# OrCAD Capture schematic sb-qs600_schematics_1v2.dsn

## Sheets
1 01. Index: title: SB-QS600    01 Index; rev: 1.2; note: 8000020000
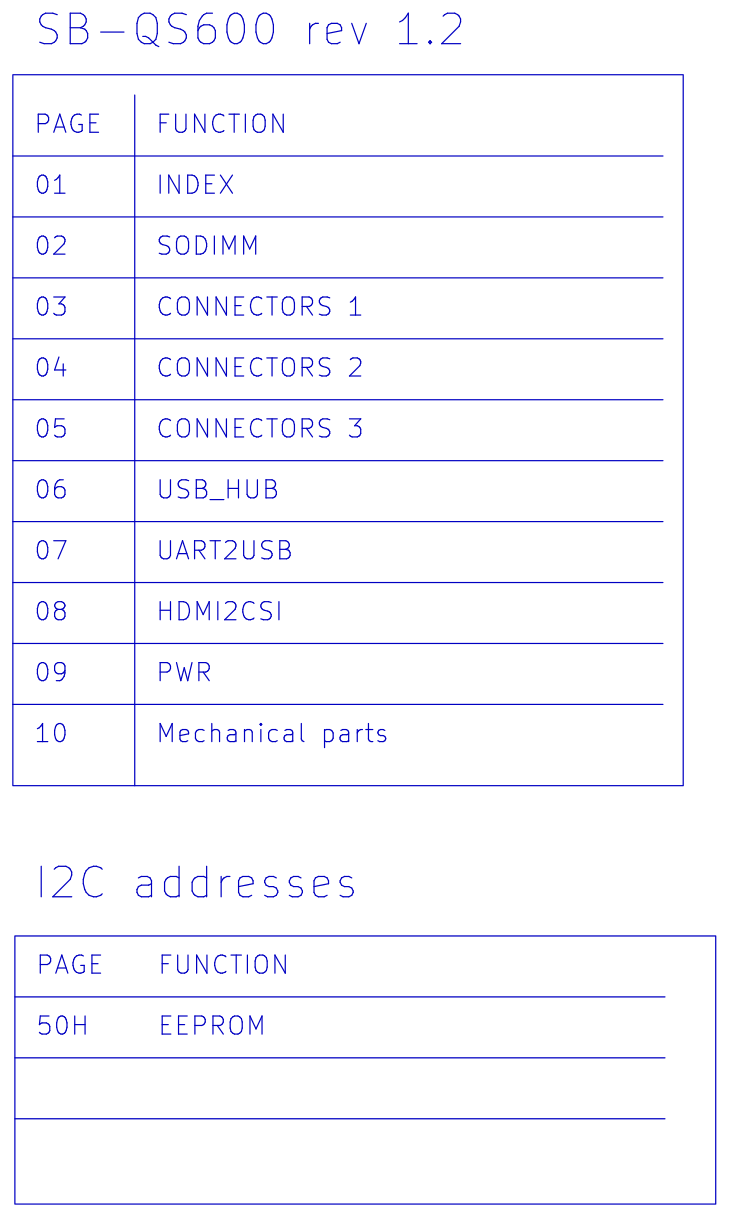
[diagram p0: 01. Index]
2 02. SODIMM: size C; title: SB-QS600    02 SODIMM
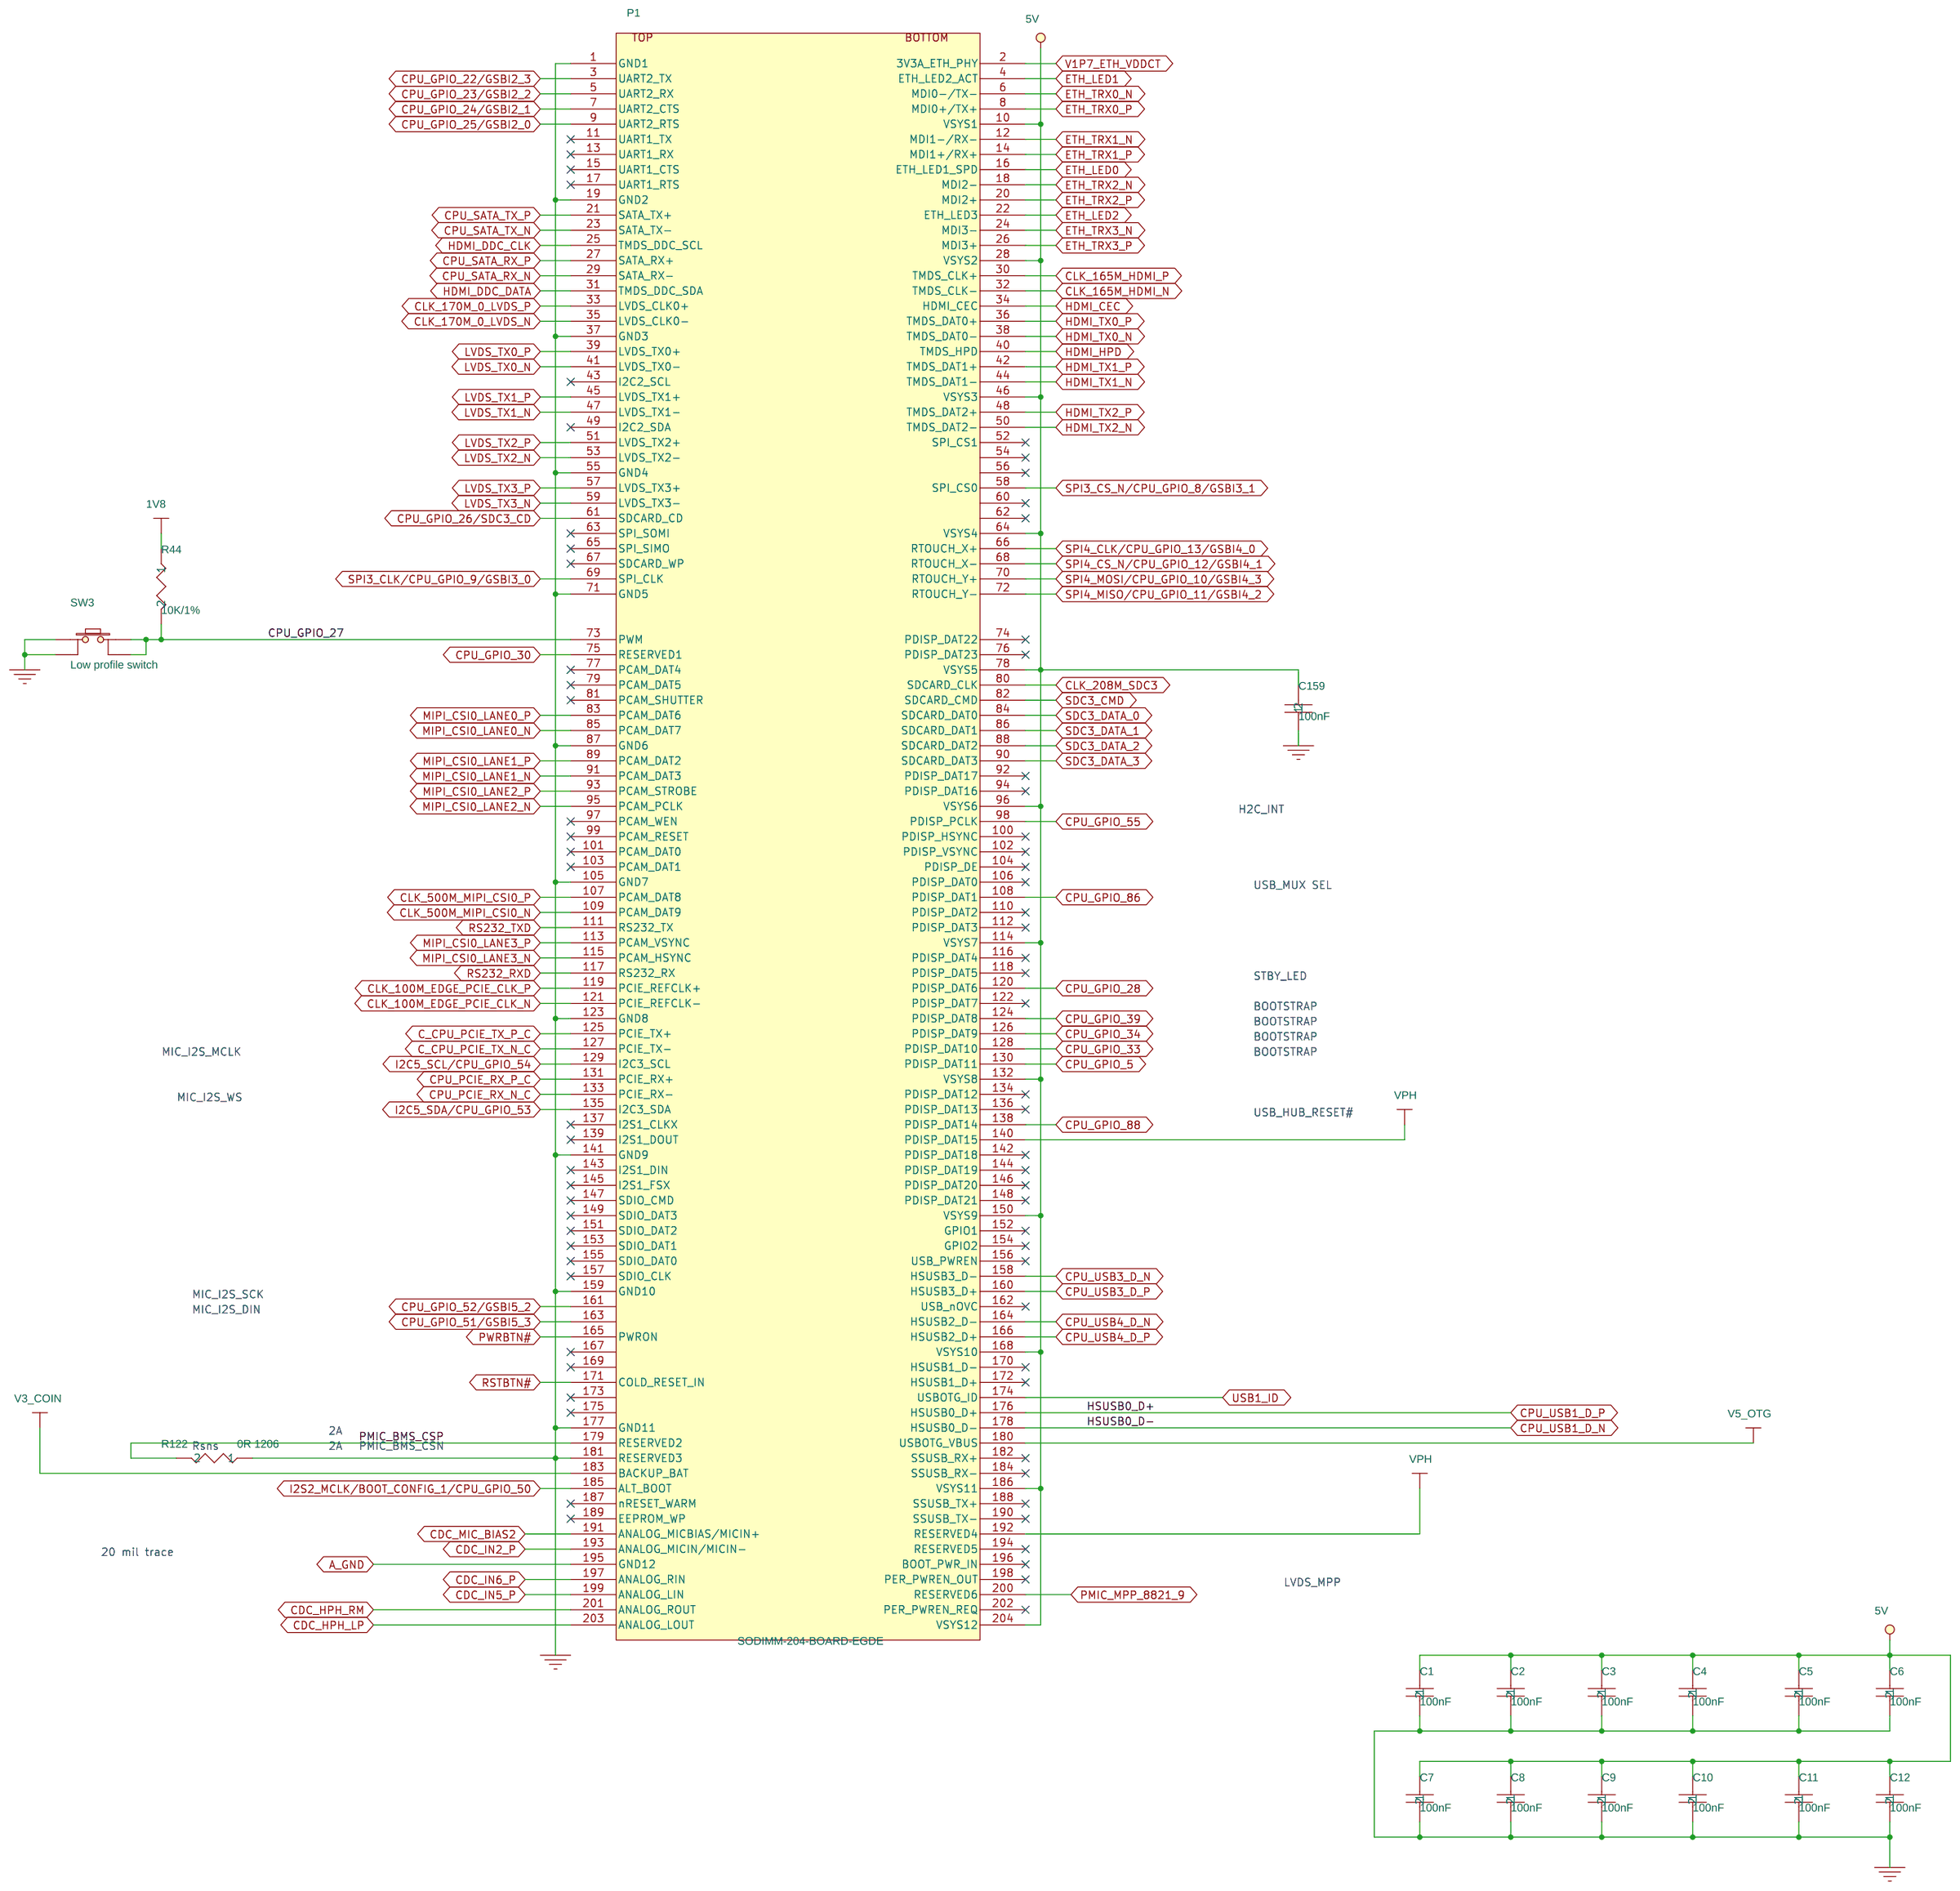
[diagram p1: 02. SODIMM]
3 03. Connectors 1: size B; title: SB-QS600    03 Connectors
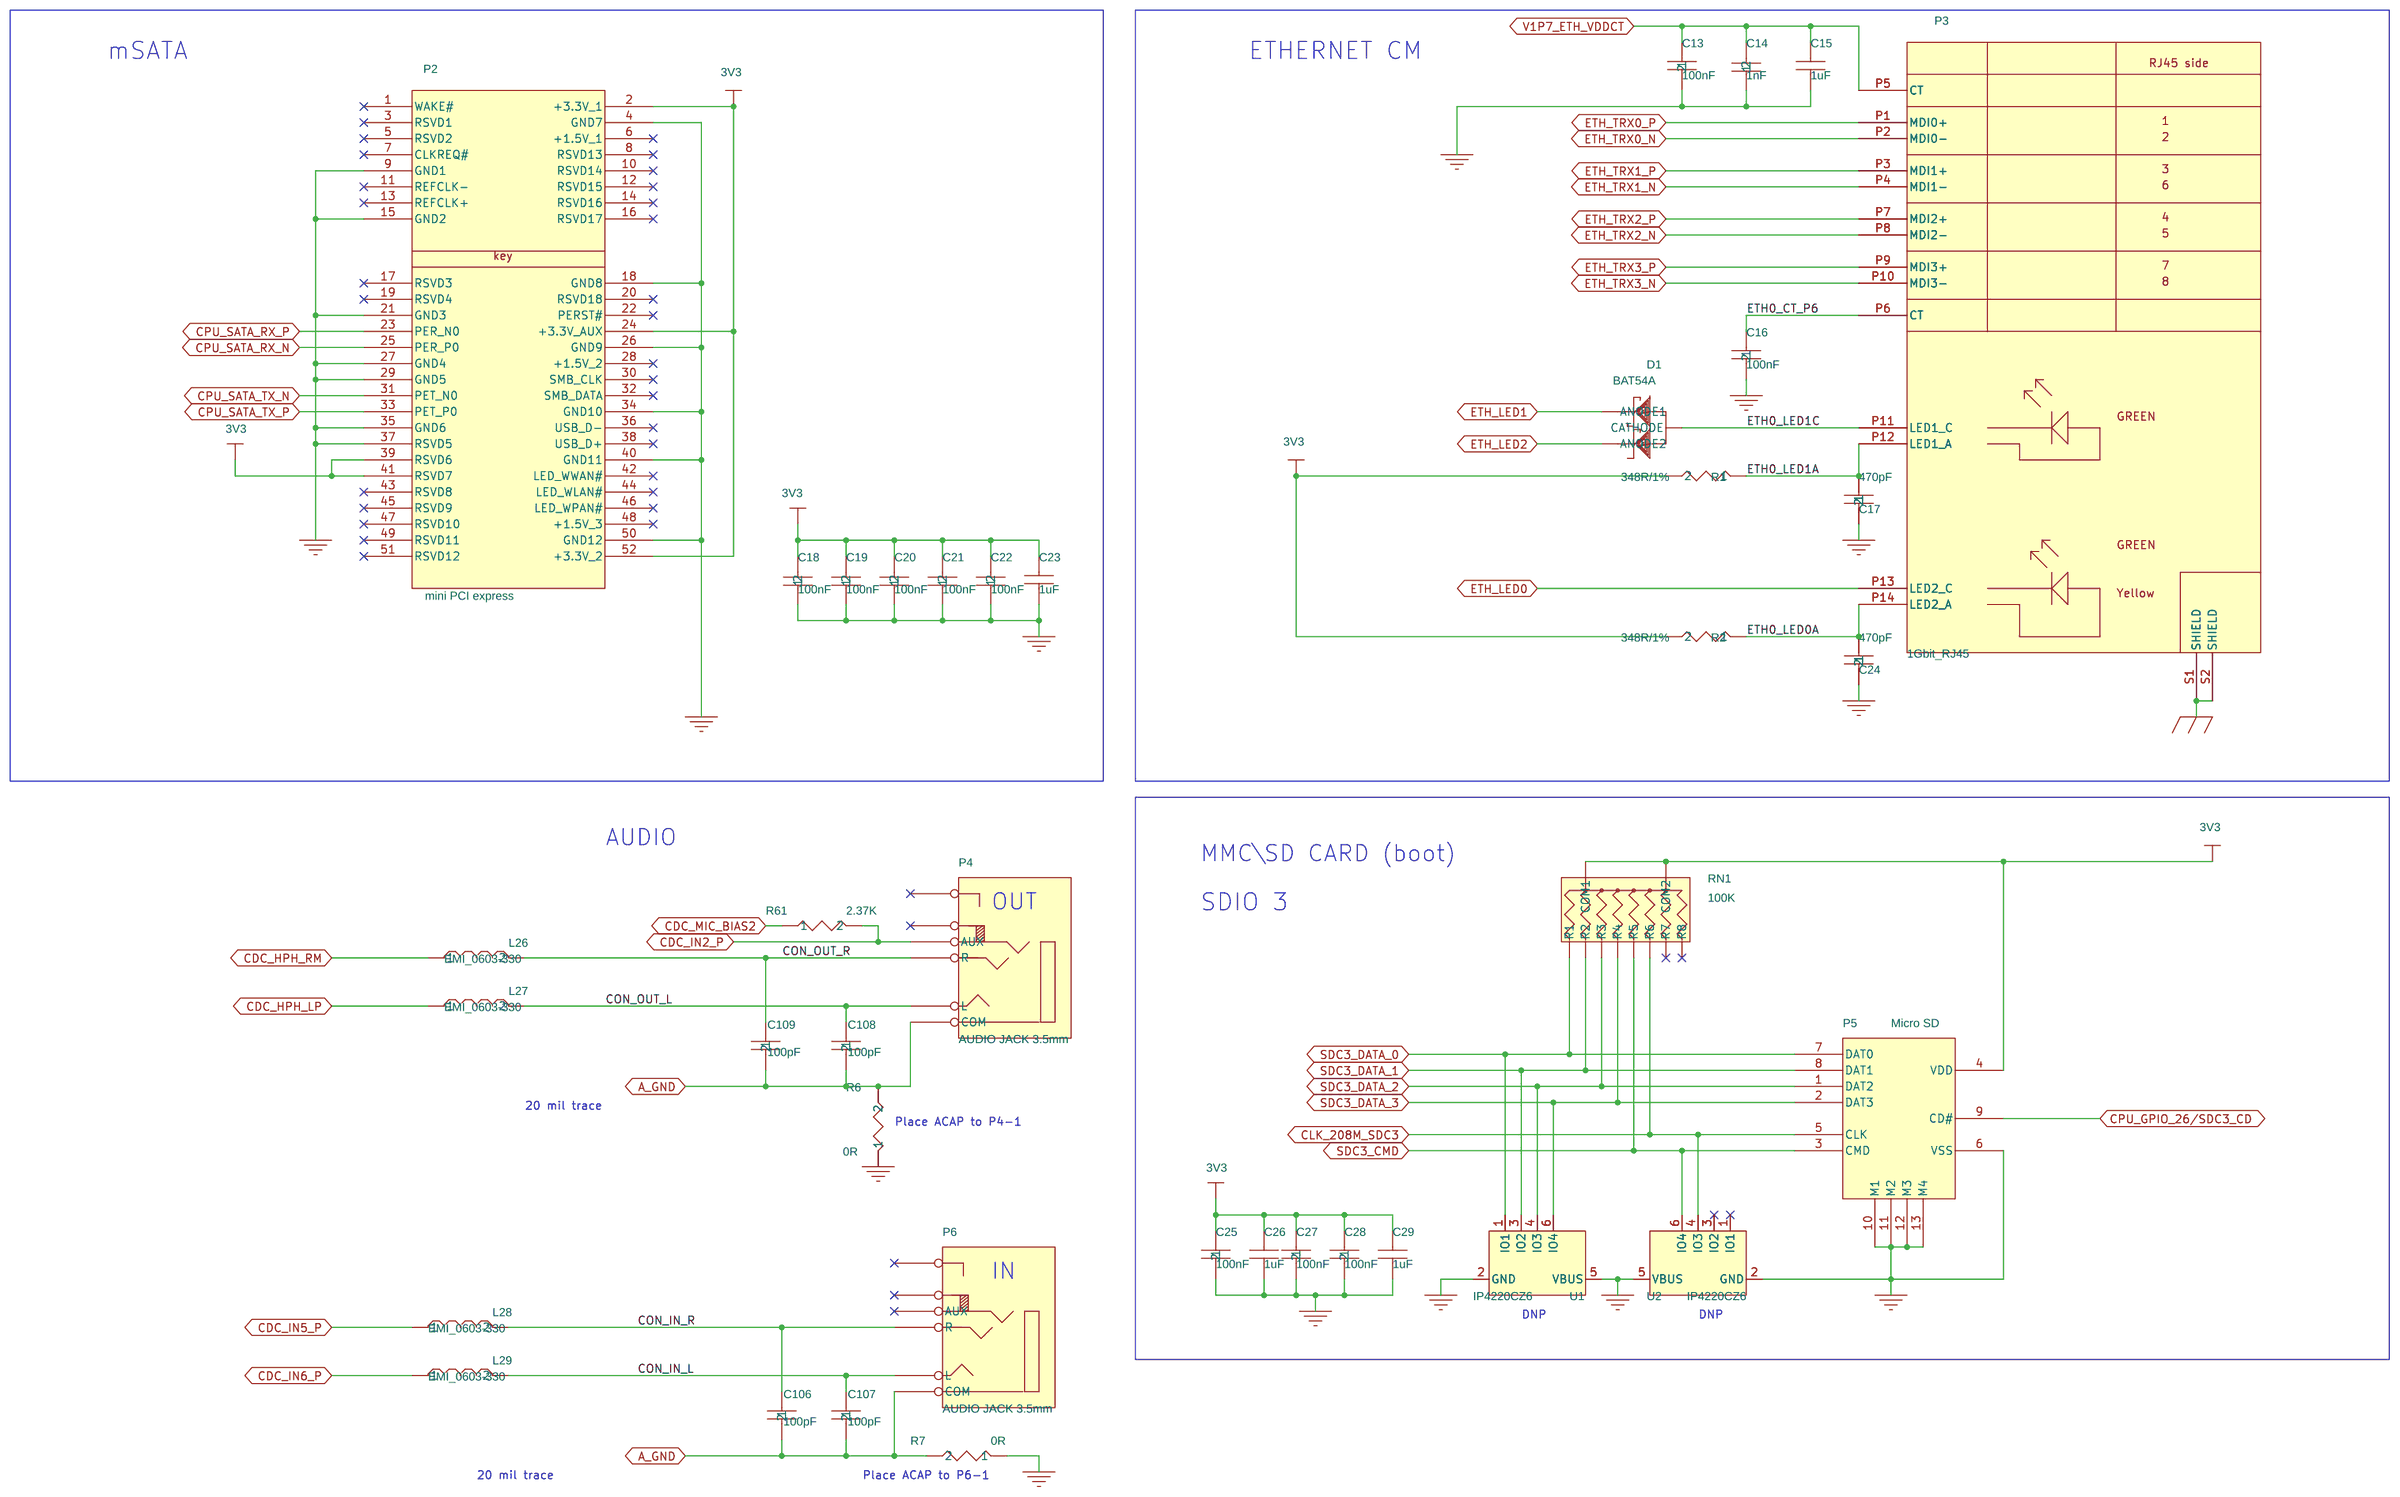
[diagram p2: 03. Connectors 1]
4 04. Connectors 2: size B; title: SB-QS600    04 Connectors 2
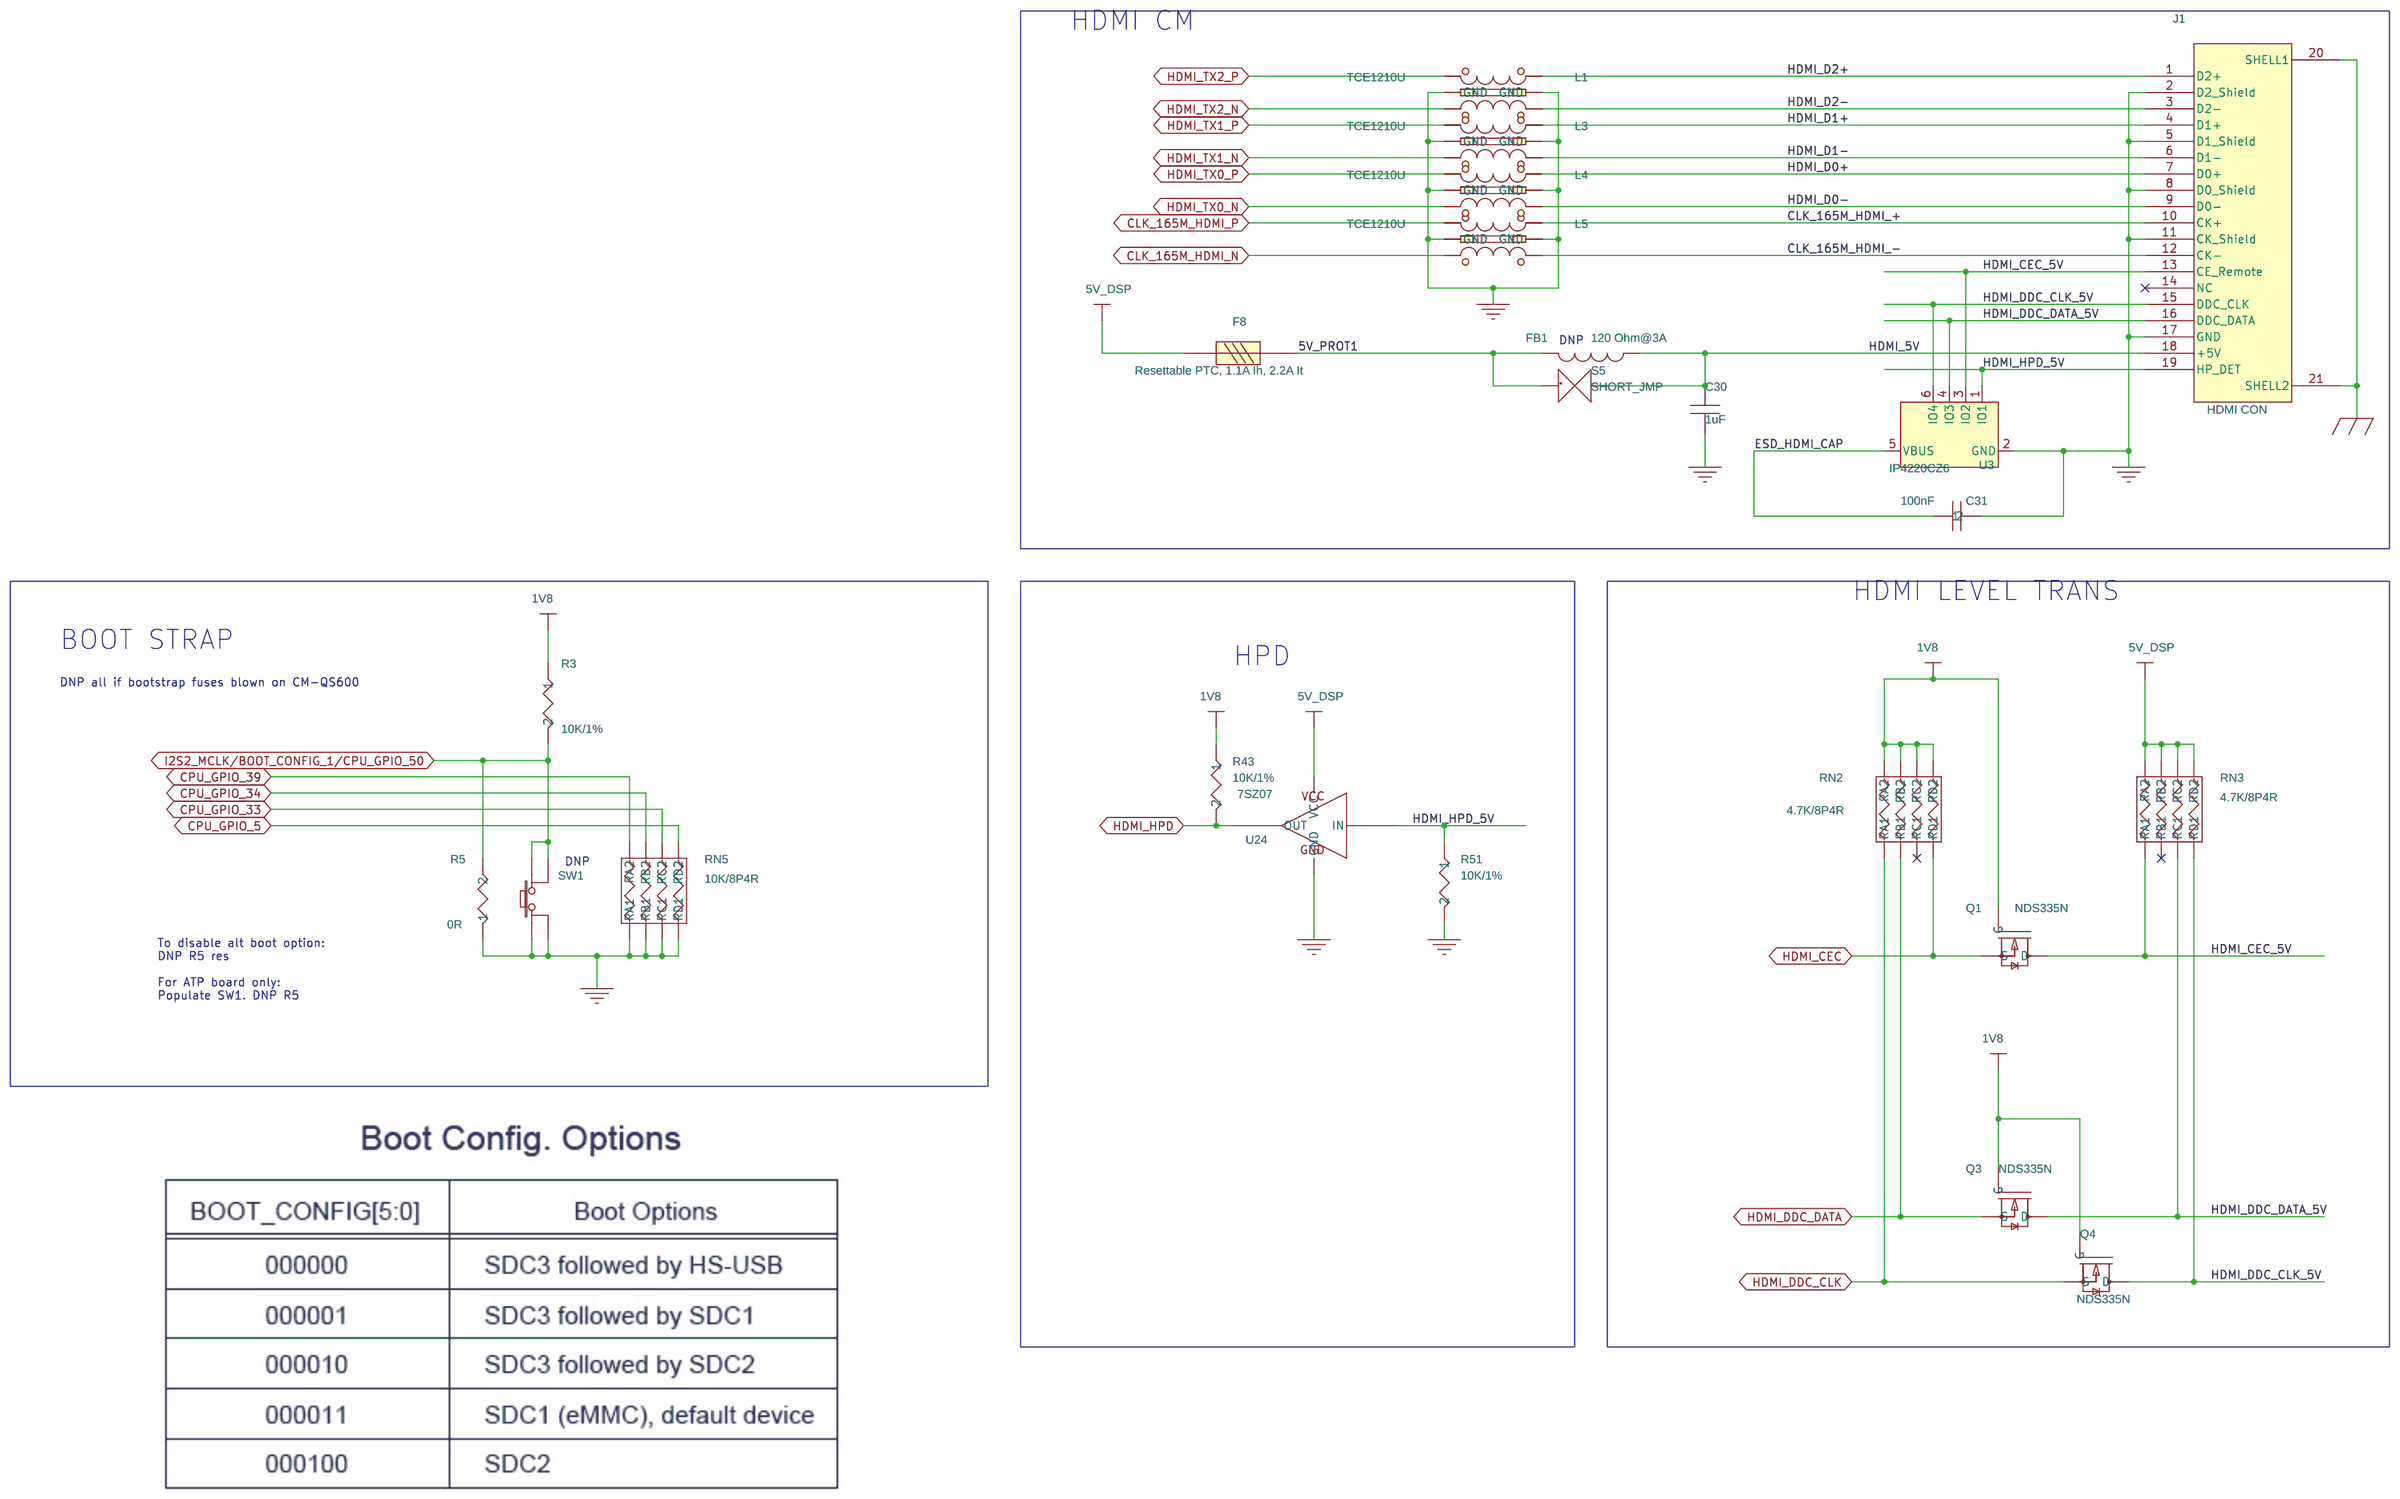
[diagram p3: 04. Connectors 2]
5 05. Connectors 3: size B; title: SB-QS600    03 Connectors 3
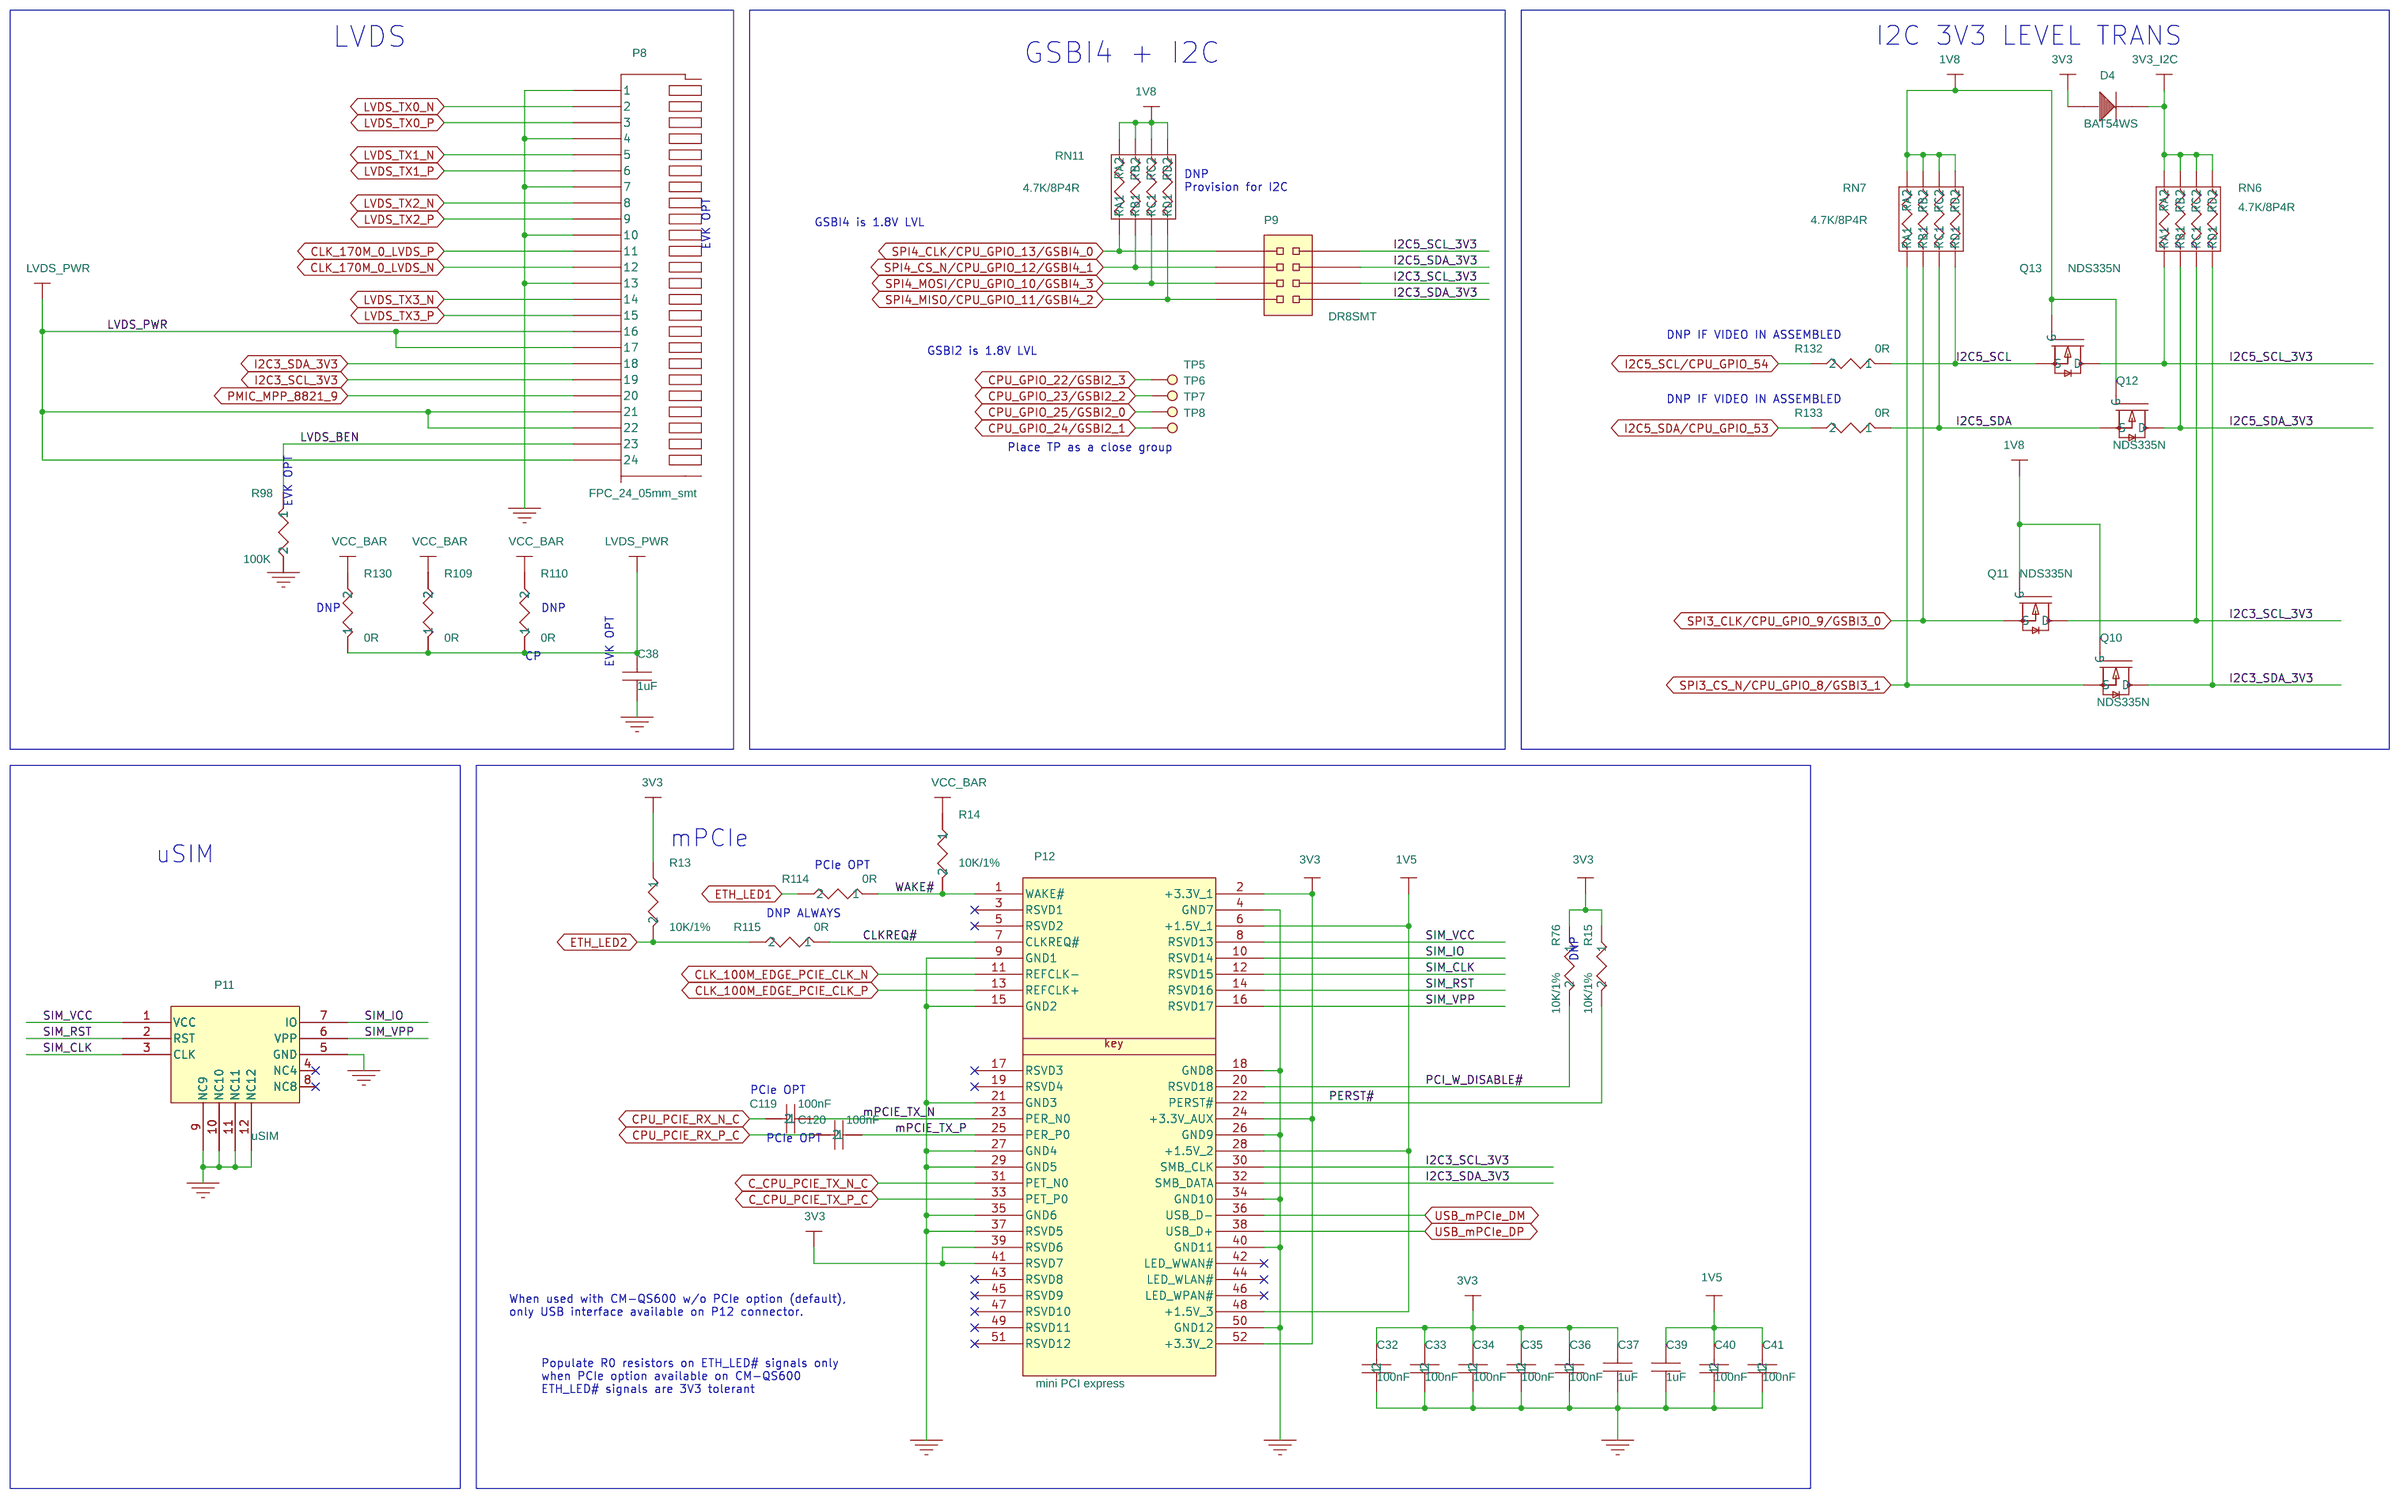
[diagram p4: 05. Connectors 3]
6 06. USB_HUB: size C; title: SB-QS600    USB HUB; note: 8001006002
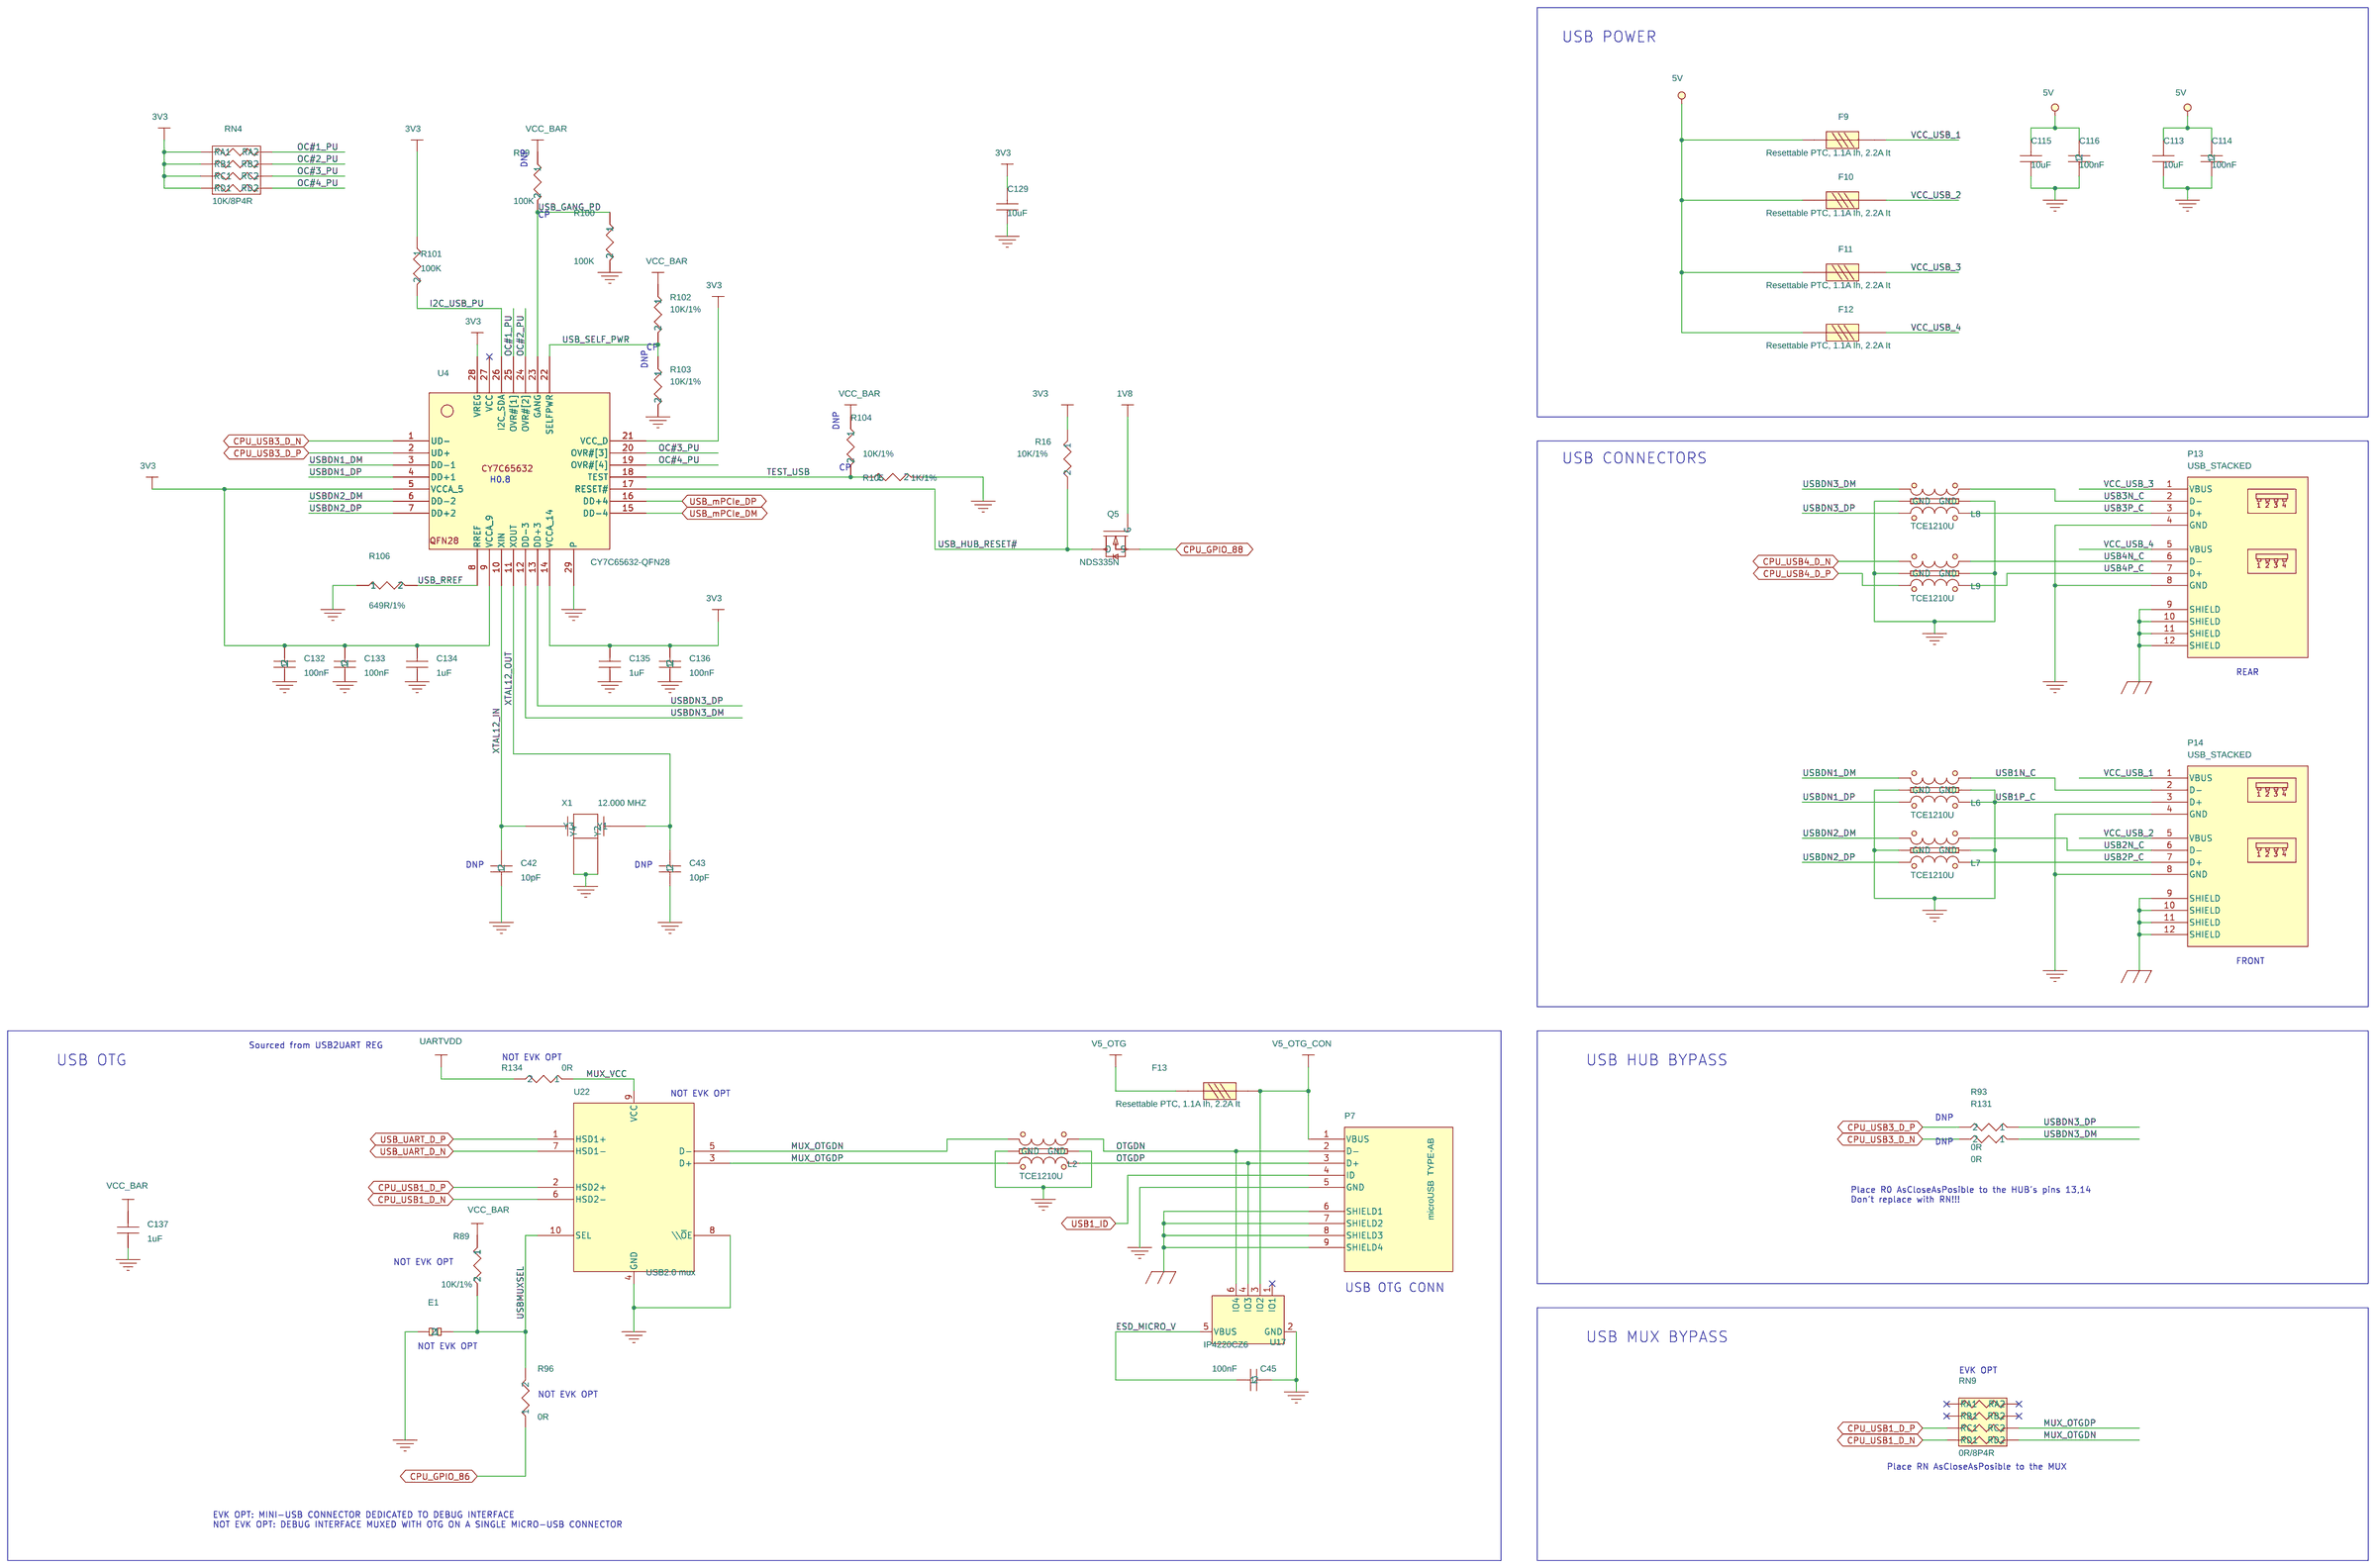
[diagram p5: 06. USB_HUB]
7 07. UART2USB_EEPROM: size B; title: SB-QS600    07 UART2USB, EEPROM
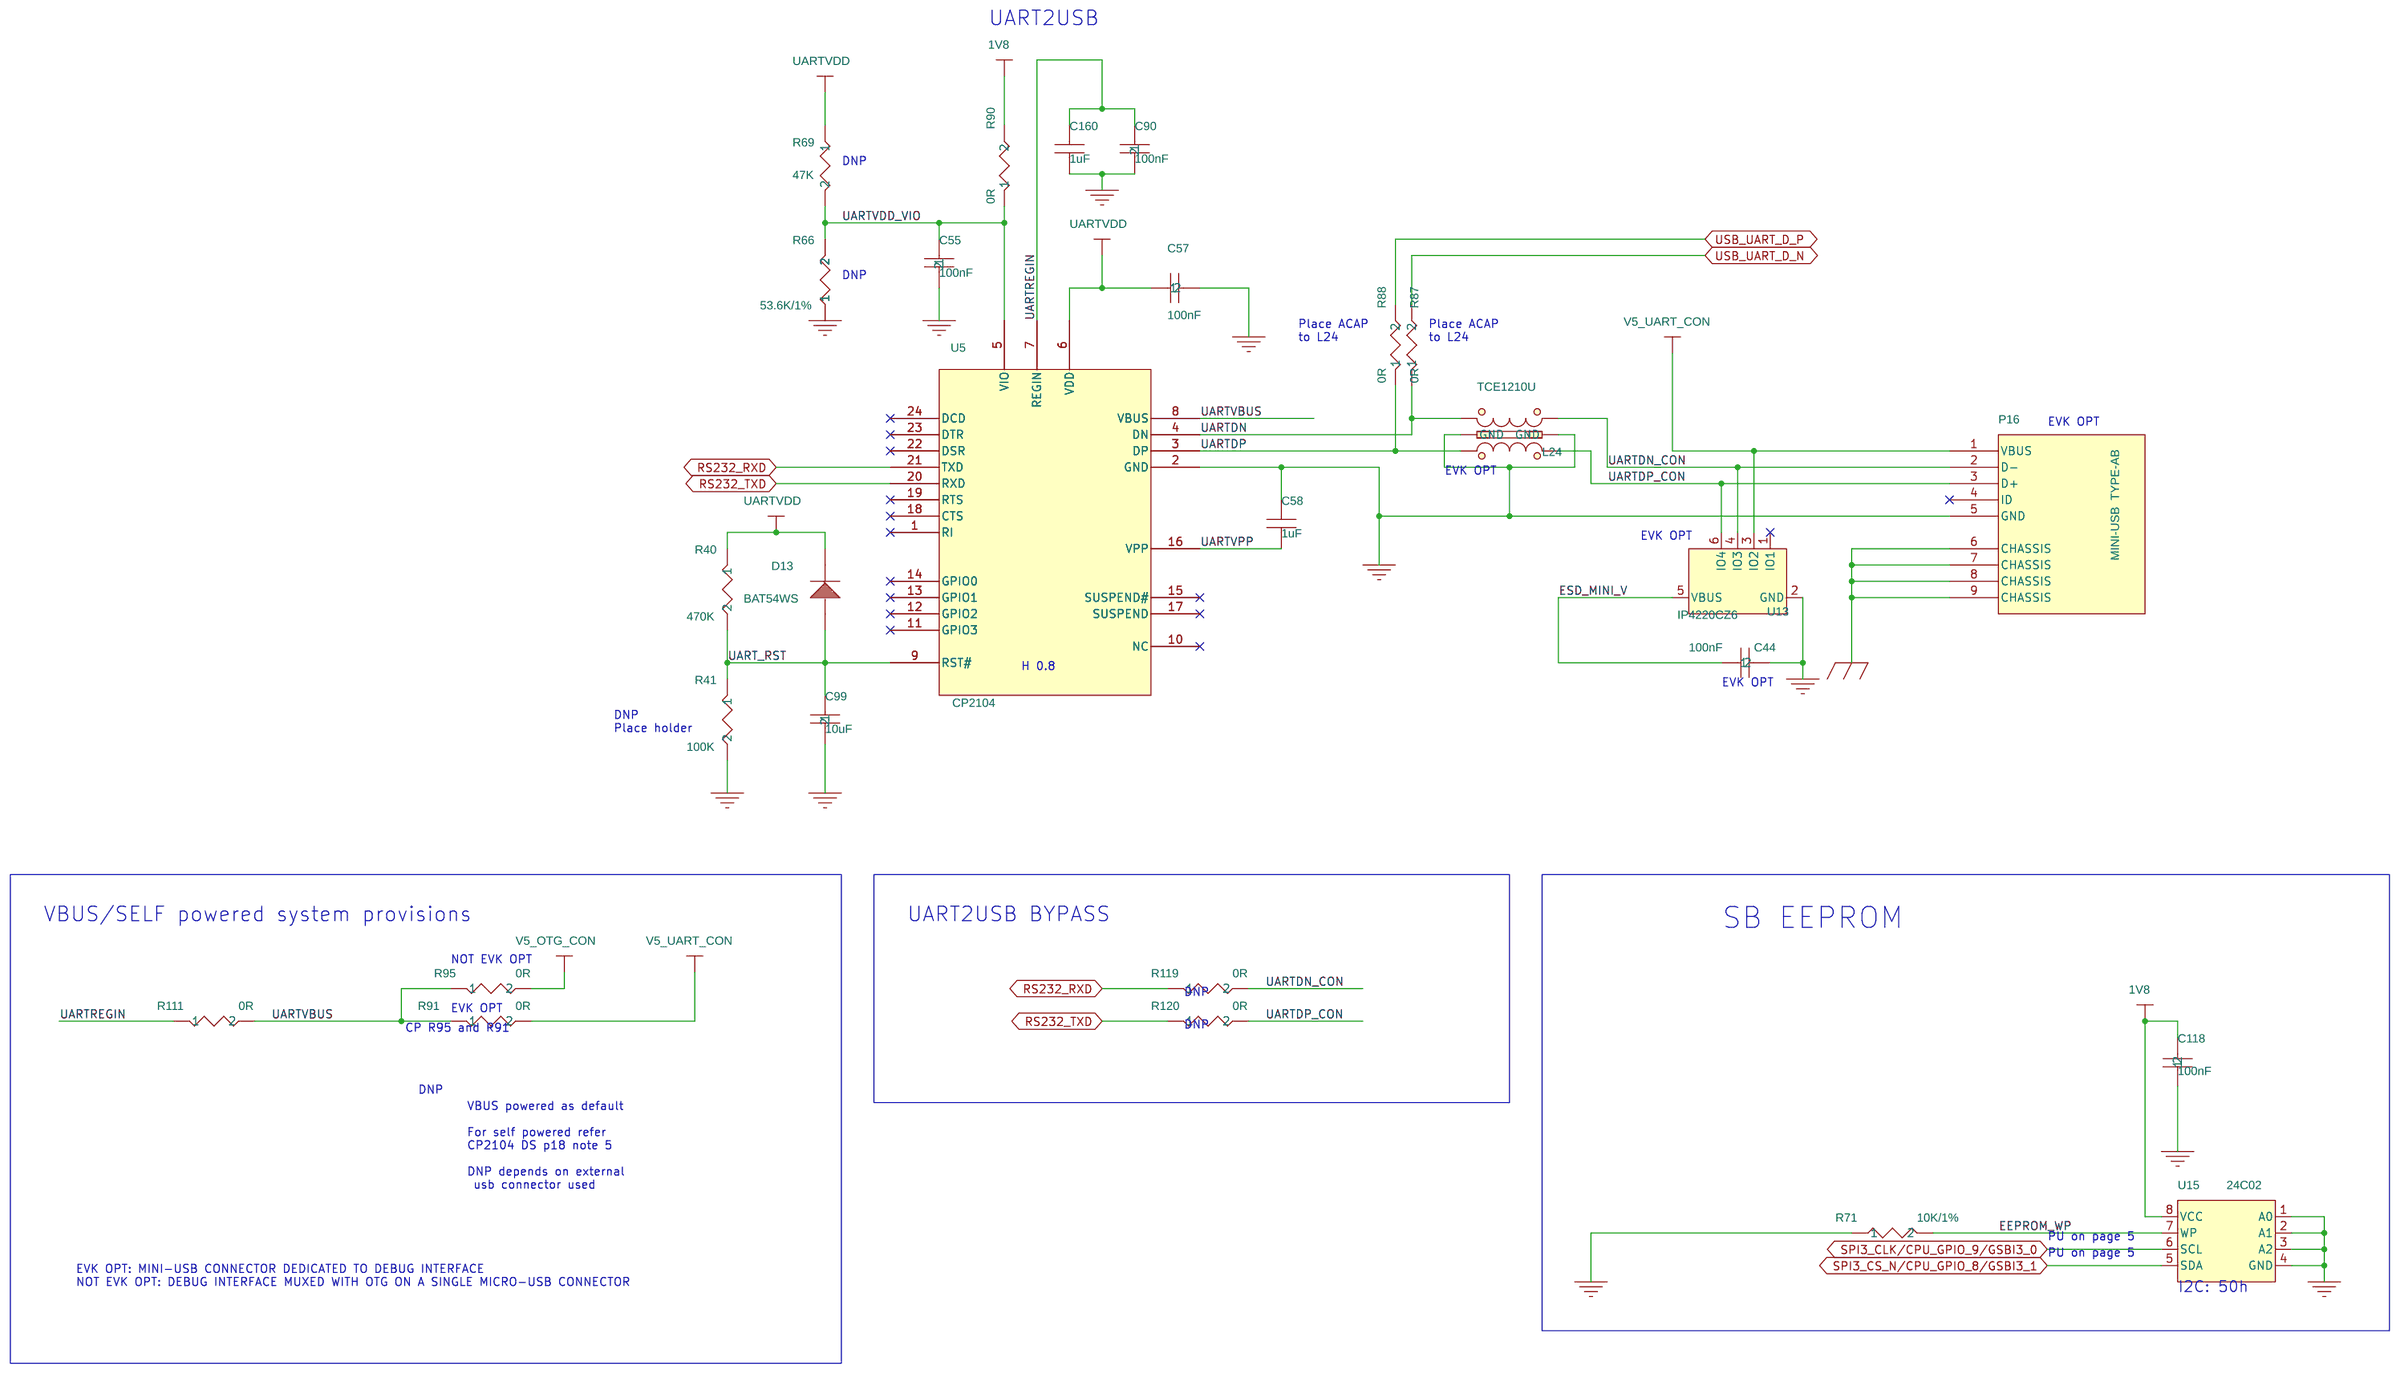
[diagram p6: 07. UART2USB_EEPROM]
8 08. HDMI2CSI: size C; title: SB-QS600    08 HDMI2CSI
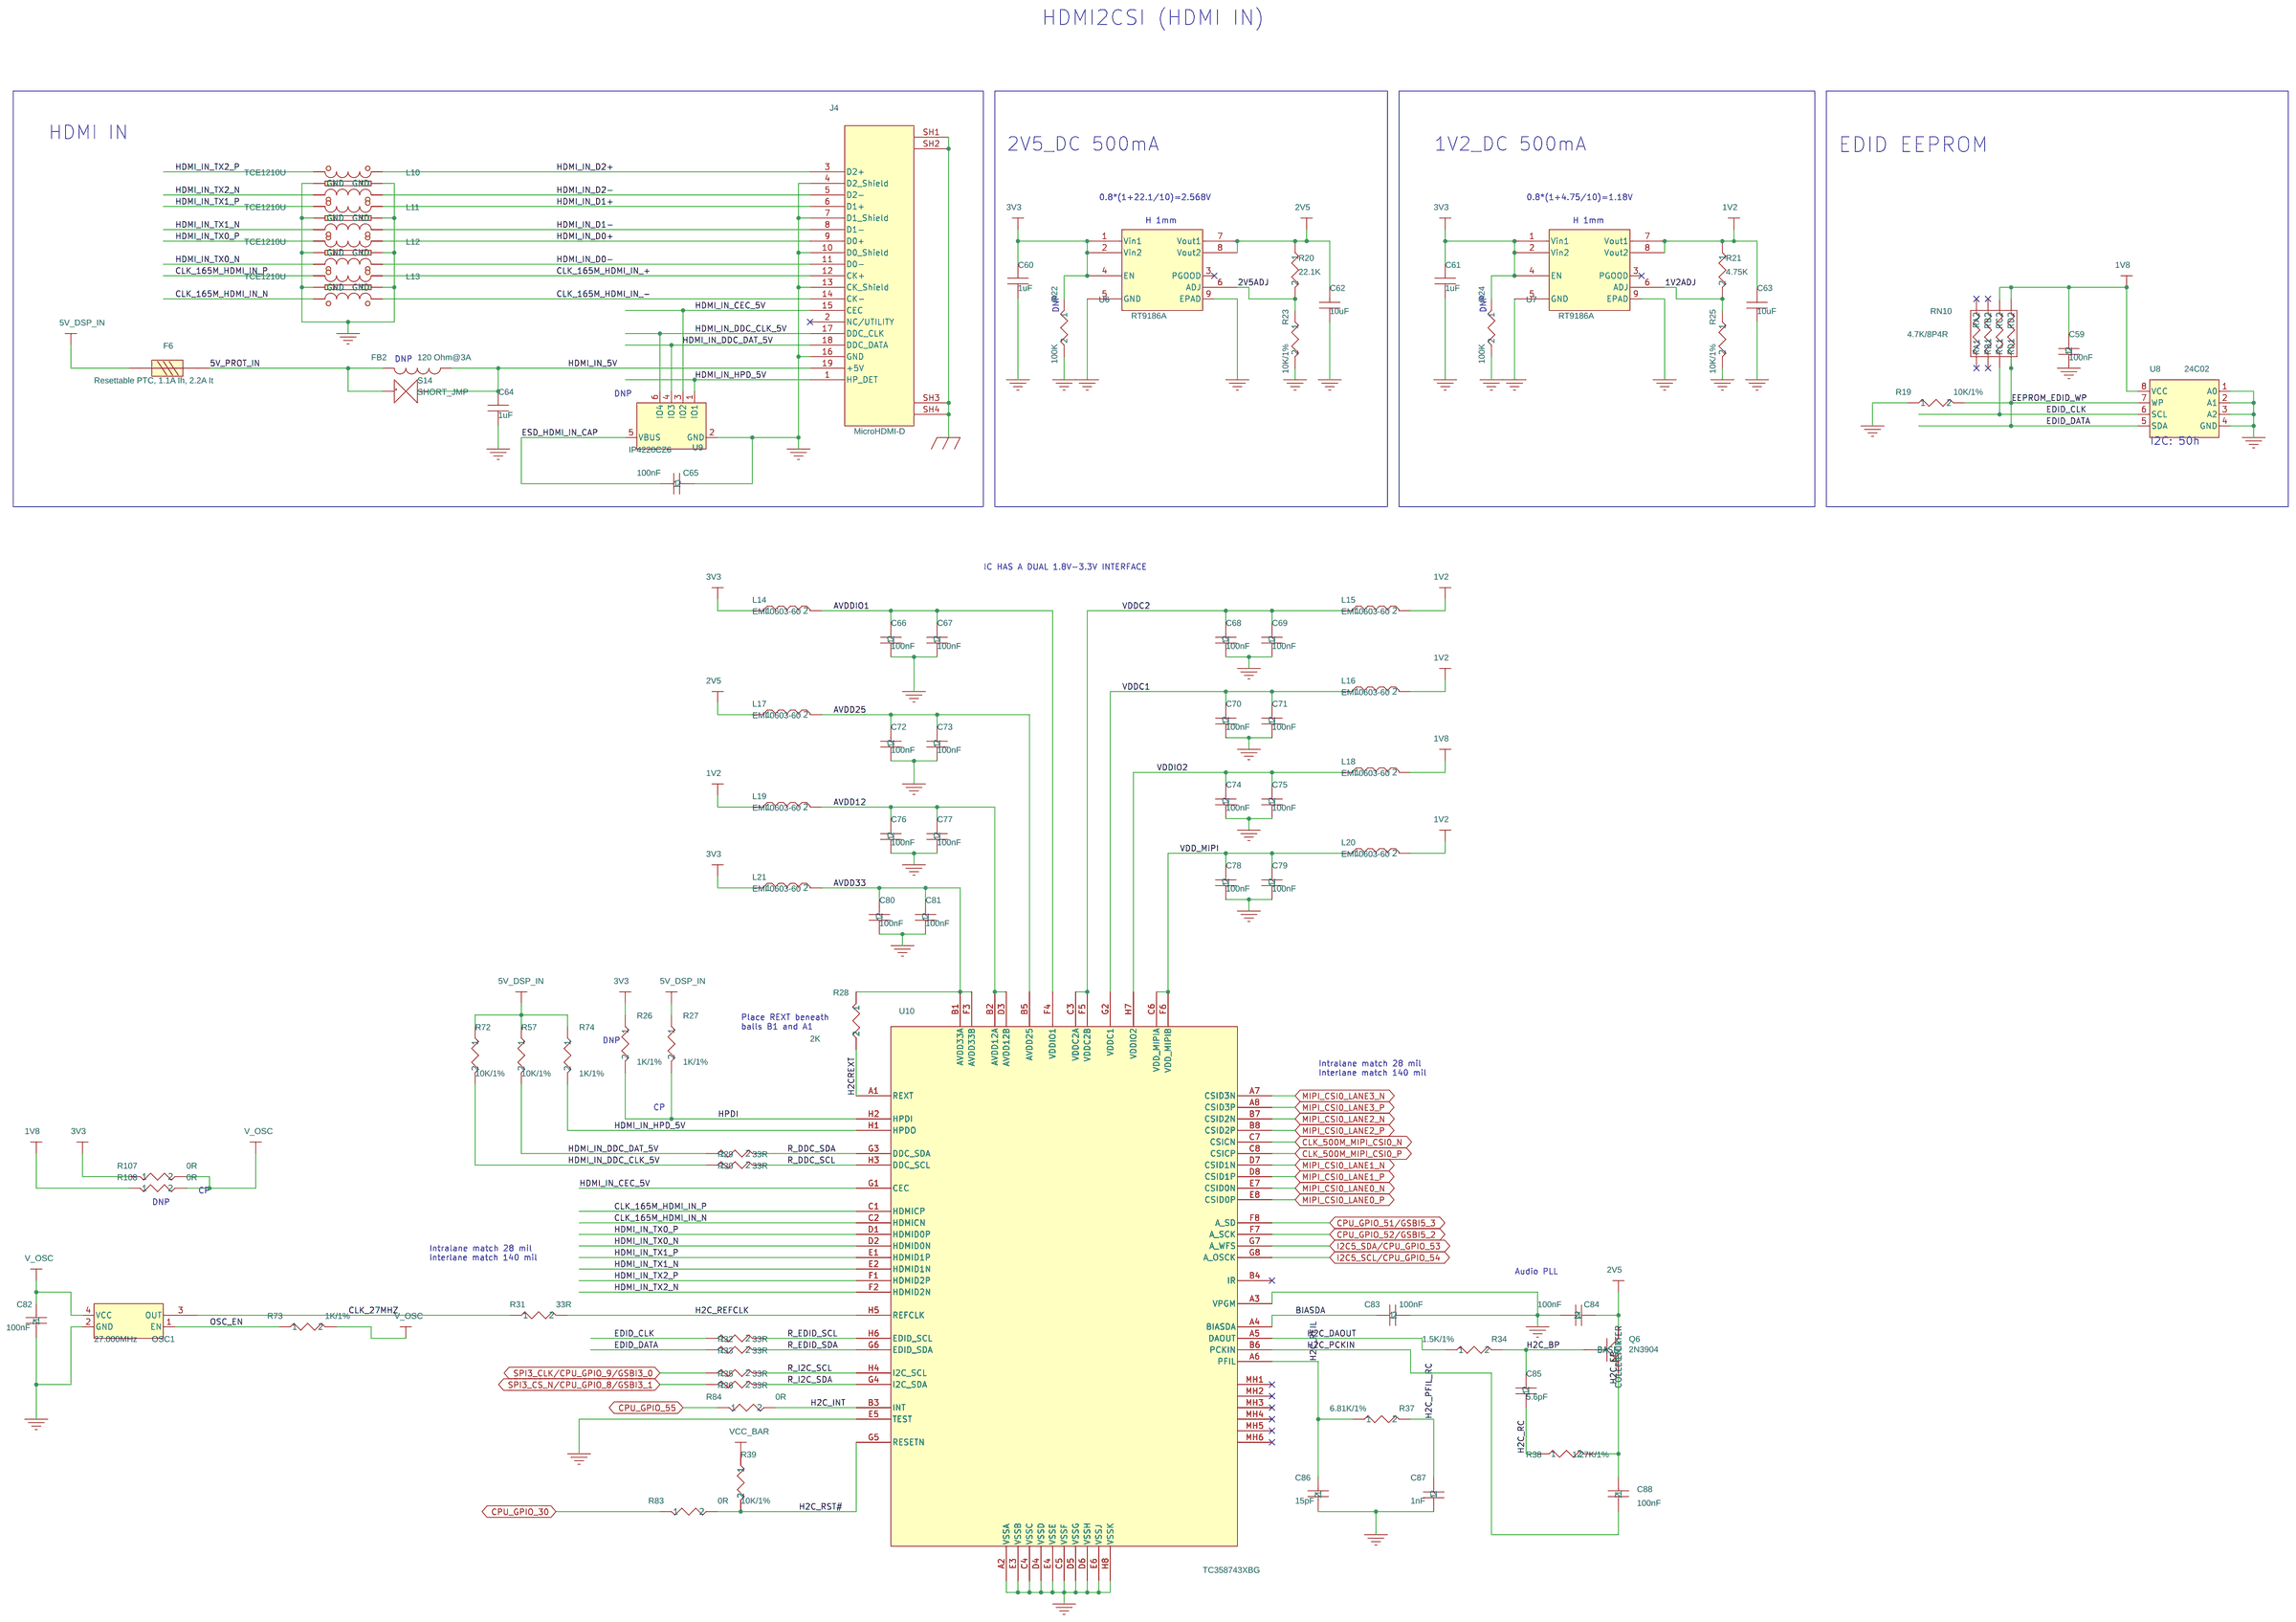
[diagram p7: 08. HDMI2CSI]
9 09. PWR: size B; title: SB-QS600    09 POWER
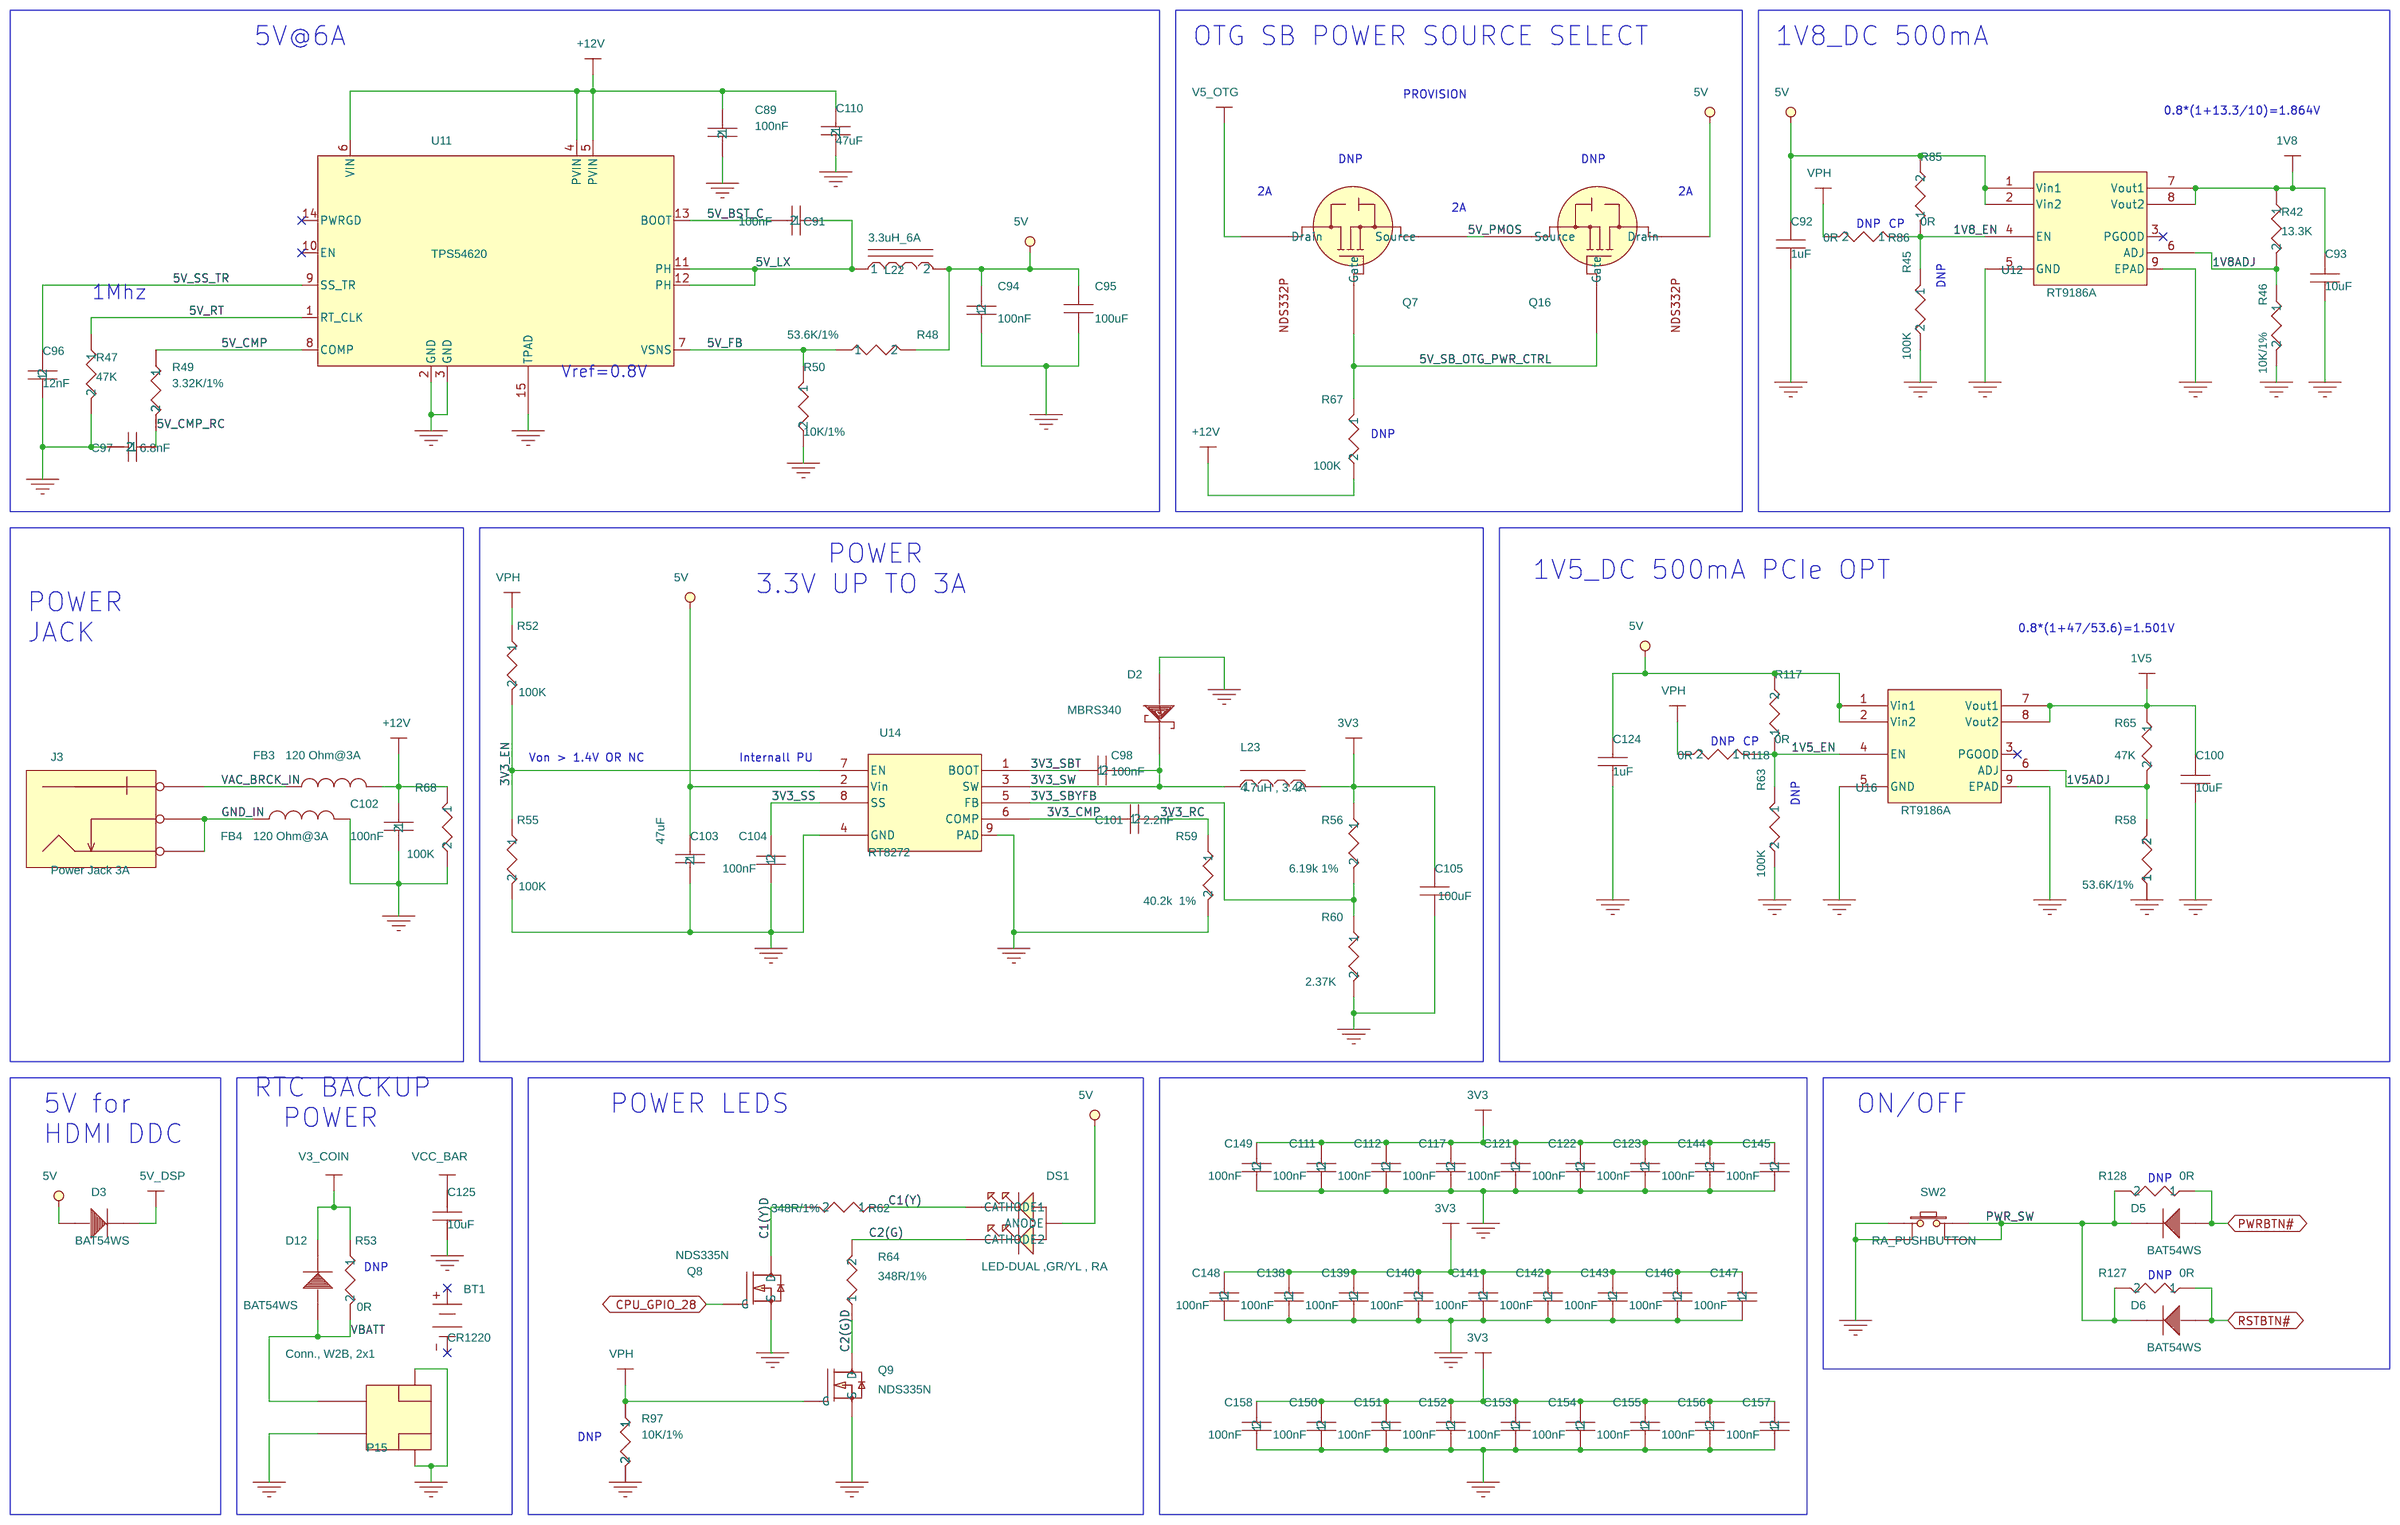
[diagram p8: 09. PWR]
10 10. Mechanical parts: size B; title: SB-QS600    10 MECHANICS
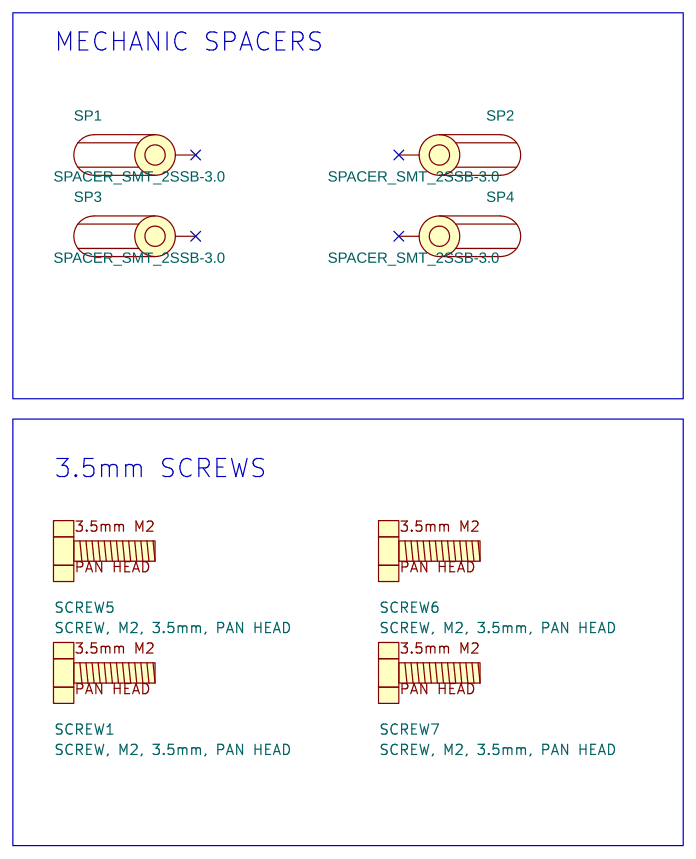
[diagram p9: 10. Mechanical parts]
11 12. Notes: title: SB-QS600    12 NTES
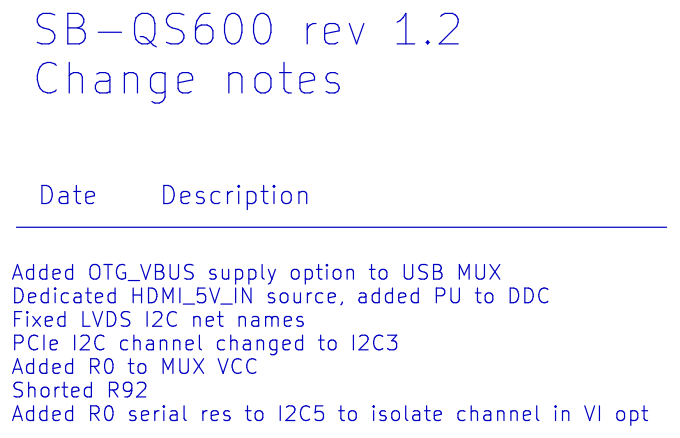
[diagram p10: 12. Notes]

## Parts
sheet 02. SODIMM
C1  100nF  [RC0402]
C2  100nF  [RC0402]
C3  100nF  [RC0402]
C4  100nF  [RC0402]
C5  100nF  [RC0402]
C6  100nF  [RC0402]
C7  100nF  [RC0402]
C8  100nF  [RC0402]
C9  100nF  [RC0402]
C10  100nF  [RC0402]
C11  100nF  [RC0402]
C12  100nF  [RC0402]
C159  100nF  [RC0402]
P1  SODIMM-204-BOARD-EGDE  [SODIMM204-EDGE]
R44  10K/1%  [RC0402]
R122  0R 1206  [RC0402]
SW3  Low profile switch  [TACSW4x6SMRA]
sheet 03. Connectors 1
C13  100nF  [RC0402]
C14  1nF  [RC0402]
C15  1uF  [RC0402]
C16  100nF  [RC0402]
C17  470pF  [RC0603]
C18  100nF  [RC0402]
C19  100nF  [RC0402]
C20  100nF  [RC0402]
C21  100nF  [RC0402]
C22  100nF  [RC0402]
C23  1uF  [RC0402]
C24  470pF  [RC0603]
C25  100nF  [RC0402]
C26  1uF  [RC0402]
C27  100nF  [RC0402]
C28  100nF  [RC0402]
C29  1uF  [RC0402]
C106  100pF  [RC0402]
C107  100pF  [RC0402]
C108  100pF  [RC0402]
C109  100pF  [RC0402]
D1  BAT54A  [SOT23]
L26  EMI_0603-330  [FB0603]
L27  EMI_0603-330  [FB0603]
L28  EMI_0603-330  [FB0603]
L29  EMI_0603-330  [FB0603]
P2  mini PCI express  [MINIPCIE-4]
P3  1Gbit_RJ45  [DUSBRJ-1G]
P4  AUDIO JACK 3.5mm  [AJ35-4P-SW-SM]
P5  Micro SD  [MicroSD-PP-RA-SM]
P6  AUDIO JACK 3.5mm  [AJ35-4P-SW-SM]
R1  348R/1%  [RC0402]
R2  348R/1%  [RC0402]
R6  0R  [RC0402]
R7  0R  [RC0402]
R61  2.37K  [RC0402]
RN1  100K  [RESNET10P1206]
U1  IP4220CZ6  [SOT23-6L]
U2  IP4220CZ6  [SOT23-6L]
sheet 04. Connectors 2
C30  1uF  [RC0402]
C31  100nF  [RC0402]
F8  Resettable PTC, 1.1A Ih, 2.2A It  [FUSE-1206]
FB1  120 Ohm@3A  [1206]
J1  HDMI CON  [HDMI-A19-RASM]
L1  TCE1210U  [EMI1012-ESD]
L3  TCE1210U  [EMI1012-ESD]
L4  TCE1210U  [EMI1012-ESD]
L5  TCE1210U  [EMI1012-ESD]
Q1  NDS335N  [SOT23]
Q3  NDS335N  [SOT23]
Q4  NDS335N  [SOT23]
R3  10K/1%  [RC0402]
R5  0R  [RC0402]
R43  10K/1%  [RC0402]
R51  10K/1%  [RC0402]
RN2  4.7K/8P4R  [RESNET8P0805]
RN3  4.7K/8P4R  [RESNET8P0805]
RN5  10K/8P4R  [RESNET8P0805]
S5  SHORT_JMP  [SHORT_SMT]
SW1  Low profile switch  [TACSW4x6SMRA]
U3  IP4220CZ6  [SOT23-6L]
U24  7SZ07  [SC70]
sheet 05. Connectors 3
C32  100nF  [RC0402]
C33  100nF  [RC0402]
C34  100nF  [RC0402]
C35  100nF  [RC0402]
C36  100nF  [RC0402]
C37  1uF  [RC0402]
C38  1uF  [RC0402]
C39  1uF  [RC0402]
C40  100nF  [RC0402]
C41  100nF  [RC0402]
C119  100nF  [RC0402]
C120  100nF  [RC0402]
D4  BAT54WS  [SOD-323]
P8  FPC_24_05mm_smt
P9  DR8SMT  [2X4SMHDR]
P11  uSIM  [SKT-MicroSIM6-SM]
P12  mini PCI express  [MINIPCIE-4]
Q10  NDS335N  [SOT23]
Q11  NDS335N  [SOT23]
Q12  NDS335N  [SOT23]
Q13  NDS335N  [SOT23]
R13  10K/1%  [RC0402]
R14  10K/1%  [RC0402]
R15  10K/1%  [RC0402]
R76  10K/1%  [RC0402]
R98  100K  [RC0402]
R109  0R  [RC0402]
R110  0R  [RC0402]
R114  0R  [RC0402]
R115  0R  [RC0402]
R130  0R  [RC0402]
R132  0R  [RC0402]
R133  0R  [RC0402]
RN6  4.7K/8P4R  [RESNET8P0805]
RN7  4.7K/8P4R  [RESNET8P0805]
RN11  4.7K/8P4R  [RESNET8P0805]
TP5  TESTPOINT  [TESTPOINT]
TP6  TESTPOINT  [TESTPOINT]
TP7  TESTPOINT  [TESTPOINT]
TP8  TESTPOINT  [TESTPOINT]
sheet 06. USB_HUB
C42  10pF  [RC0402]
C43  10pF  [RC0402]
C45  100nF  [RC0402]
C113  10uF  [RC0603]
C114  100nF  [RC0402]
C115  10uF  [RC0603]
C116  100nF  [RC0402]
C129  10uF  [RC0603]
C132  100nF  [RC0402]
C133  100nF  [RC0402]
C134  1uF  [RC0402]
C135  1uF  [RC0402]
C136  100nF  [RC0402]
C137  1uF  [RC0402]
E1  HDR1X2  [1X2THHDR]
F9  Resettable PTC, 1.1A Ih, 2.2A It  [FUSE-1206]
F10  Resettable PTC, 1.1A Ih, 2.2A It  [FUSE-1206]
F11  Resettable PTC, 1.1A Ih, 2.2A It  [FUSE-1206]
F12  Resettable PTC, 1.1A Ih, 2.2A It  [FUSE-1206]
F13  Resettable PTC, 1.1A Ih, 2.2A It  [FUSE-1206]
L2  TCE1210U  [EMI1012-ESD]
L6  TCE1210U  [EMI1012-ESD]
L7  TCE1210U  [EMI1012-ESD]
L8  TCE1210U  [EMI1012-ESD]
L9  TCE1210U  [EMI1012-ESD]
P7  microUSB  TYPE-AB  [MICRO-USB-AB-RA-SM]
P13  USB_STACKED  [USB-2XA-TH]
P14  USB_STACKED  [USB-2XA-TH]
Q5  NDS335N  [SOT23]
R16  10K/1%  [RC0402]
R89  10K/1%  [RC0402]
R93  0R  [RC0402]
R96  0R  [RC0402]
R99  100K  [RC0402]
R100  100K  [RC0402]
R101  100K  [RC0402]
R102  10K/1%  [RC0402]
R103  10K/1%  [RC0402]
R104  10K/1%  [RC0402]
R105  1K/1%  [RC0402]
R106  649R/1%  [RC0402]
R131  0R  [RC0402]
R134  0R  [RC0402]
RN4  10K/8P4R  [RESNET8P0805]
RN9  0R/8P4R  [RESNET8P0805]
U4  CY7C65632-QFN28  [QFN28]
U17  IP4220CZ6  [SOT23-6L]
U22  USB2.0 mux  [MO-255U1418E]
X1  12.000 MHZ  [XTAL5x3-4]
sheet 07. UART2USB_EEPROM
C44  100nF  [RC0402]
C55  100nF  [RC0402]
C57  100nF  [RC0402]
C58  1uF  [RC0402]
C90  100nF  [RC0402]
C99  10uF  [C1210H2_5]
C118  100nF  [RC0402]
C160  1uF  [RC0402]
D13  BAT54WS  [SOD-323]
L24  TCE1210U  [EMI1012-ESD]
P16  MINI-USB  TYPE-AB  [MUSB-AB-SM]
R40  470K  [RC0402]
R41  100K  [RC0402]
R66  53.6K/1%  [RC0402]
R69  47K  [RC0402]
R71  10K/1%  [RC0402]
R87  0R  [RC0402]
R88  0R  [RC0402]
R90  0R  [RC0402]
R91  0R  [RC0402]
R95  0R  [RC0402]
R111  0R  [RC0402]
R119  0R  [RC0402]
R120  0R  [RC0402]
U5  CP2104  [MO-220VGGD-8]
U13  IP4220CZ6  [SOT23-6L]
U15  24C02  [MO-229VCED-2]
sheet 08. HDMI2CSI
C59  100nF  [RC0402]
C60  1uF  [RC0402]
C61  1uF  [RC0402]
C62  10uF  [RC0603]
C63  10uF  [RC0603]
C64  1uF  [RC0402]
C65  100nF  [RC0402]
C66  100nF  [RC0402]
C67  100nF  [RC0402]
C68  100nF  [RC0402]
C69  100nF  [RC0402]
C70  100nF  [RC0402]
C71  100nF  [RC0402]
C72  100nF  [RC0402]
C73  100nF  [RC0402]
C74  100nF  [RC0402]
C75  100nF  [RC0402]
C76  100nF  [RC0402]
C77  100nF  [RC0402]
C78  100nF  [RC0402]
C79  100nF  [RC0402]
C80  100nF  [RC0402]
C81  100nF  [RC0402]
C82  100nF  [RC0402]
C83  100nF  [RC0402]
C84  100nF  [RC0402]
C85  5.6pF  [RC0402]
C86  15pF  [RC0402]
C87  1nF  [RC0402]
C88  100nF  [RC0402]
F6  Resettable PTC, 1.1A Ih, 2.2A It  [FUSE-1206]
FB2  120 Ohm@3A  [1206]
J4  MicroHDMI-D  [MicroHDMI-D19-RASM]
L10  TCE1210U  [EMI1012-ESD]
L11  TCE1210U  [EMI1012-ESD]
L12  TCE1210U  [EMI1012-ESD]
L13  TCE1210U  [EMI1012-ESD]
L14  EMI 0603-60  [FB0603]
L15  EMI 0603-60  [FB0603]
L16  EMI 0603-60  [FB0603]
L17  EMI 0603-60  [FB0603]
L18  EMI 0603-60  [FB0603]
L19  EMI 0603-60  [FB0603]
L20  EMI 0603-60  [FB0603]
L21  EMI 0603-60  [FB0603]
OSC1  27.000MHz  [OSC3225]
Q6  2N3904  [SOT23]
R19  10K/1%  [RC0402]
R20  22.1K  [RC0402]
R21  4.75K  [RC0402]
R22  100K  [RC0402]
R23  10K/1%  [RC0402]
R24  100K  [RC0402]
R25  10K/1%  [RC0402]
R26  1K/1%  [RC0402]
R27  1K/1%  [RC0402]
R28  2K  [RC0402]
R29  33R  [RC0402]
R30  33R  [RC0402]
R31  33R  [RC0402]
R32  33R  [RC0402]
R33  33R  [RC0402]
R34  1.5K/1%  [RC0402]
R35  33R  [RC0402]
R36  33R  [RC0402]
R37  6.81K/1%  [RC0402]
R38  1.27K/1%  [RC0402]
R39  10K/1%  [RC0402]
R57  10K/1%  [RC0402]
R72  10K/1%  [RC0402]
R73  1K/1%  [RC0402]
R74  1K/1%  [RC0402]
R83  0R  [RC0402]
R84  0R  [RC0402]
R107  0R  [RC0402]
R108  0R  [RC0402]
RN10  4.7K/8P4R  [RESNET8P0805]
S14  SHORT_JMP  [SHORT_SMT]
U6  RT9186A  [DFN3x3-8]
U7  RT9186A  [DFN3x3-8]
U8  24C02  [MO-229VCED-2]
U9  IP4220CZ6  [SOT23-6L]
U10  TC358743XBG  [BGA-64-065-6x6]
sheet 09. PWR
BT1  CR1220  [BT1220SM]
C89  100nF  [RC0603]
C91  100nF  [RC0402]
C92  1uF  [RC0402]
C93  10uF  [RC0603]
C94  100nF  [RC0402]
C95  100uF  [C1206]
C96  12nF  [RC0402]
C97  6.8nF  [RC0402]
C98  100nF  [RC0603]
C100  10uF  [RC0603]
C101  2.2nF  [RC0402]
C102  100nF  [RC0603]
C103  47uF  [C1210H2_5]
C104  100nF  [RC0402]
C105  100uF  [C1206]
C110  47uF  [C1210H2_5]
C111  100nF  [RC0402]
C112  100nF  [RC0402]
C117  100nF  [RC0402]
C121  100nF  [RC0402]
C122  100nF  [RC0402]
C123  100nF  [RC0402]
C124  1uF  [RC0402]
C125  10uF  [RC0603]
C138  100nF  [RC0402]
C139  100nF  [RC0402]
C140  100nF  [RC0402]
C141  100nF  [RC0402]
C142  100nF  [RC0402]
C143  100nF  [RC0402]
C144  100nF  [RC0402]
C145  100nF  [RC0402]
C146  100nF  [RC0402]
C147  100nF  [RC0402]
C148  100nF  [RC0402]
C149  100nF  [RC0402]
C150  100nF  [RC0402]
C151  100nF  [RC0402]
C152  100nF  [RC0402]
C153  100nF  [RC0402]
C154  100nF  [RC0402]
C155  100nF  [RC0402]
C156  100nF  [RC0402]
C157  100nF  [RC0402]
C158  100nF  [RC0402]
D2  MBRS340  [DO-214AB]
D3  BAT54WS  [SOD-323]
D5  BAT54WS  [SOD-323]
D6  BAT54WS  [SOD-323]
D12  BAT54WS  [SOD-323]
DS1  LED-DUAL ,GR/YL , RA  [LED3x1RASM]
FB3  120 Ohm@3A  [1206]
FB4  120 Ohm@3A  [1206]
J3  Power Jack 3A  [PJ-0210-TH]
L22  3.3uH_6A  [IND55x55_2SM]
L23  4.7uH , 3.4A  [IND7_3x7_3SM]
P15  Conn., W2B, 2x1  [1x2W2B1_25RASM]
Q7  NDS332P  [SOT23]
Q8  NDS335N  [SOT23]
Q9  NDS335N  [SOT23]
Q16  NDS332P  [SOT23]
R42  13.3K  [RC0402]
R45  100K  [RC0402]
R46  10K/1%  [RC0402]
R47  47K  [RC0402]
R48  53.6K/1%  [RC0402]
R49  3.32K/1%  [RC0402]
R50  10K/1%  [RC0402]
R52  100K  [RC0402]
R53  0R  [RC0402]
R55  100K  [RC0402]
R56  6.19k 1%  [RC0402]
R58  53.6K/1%  [RC0402]
R59  40.2k  1%  [RC0402]
R60  2.37K  [RC0402]
R62  348R/1%  [RC0402]
R63  100K  [RC0402]
R64  348R/1%  [RC0402]
R65  47K  [RC0402]
R67  100K  [RC0402]
R68  100K  [RC0402]
R85  0R  [RC0402]
R86  0R  [RC0402]
R97  10K/1%  [RC0402]
R117  0R  [RC0402]
R118  0R  [RC0402]
R127  0R  [RC0402]
R128  0R  [RC0402]
SW2  RA_PUSHBUTTON  [TACSW4x6SMRA]
U11  TPS54620  [VQFN, 3.5x3.5mm]
U12  RT9186A  [DFN3x3-8]
U14  RT8272  [PSOP-8-2X2]
U16  RT9186A  [DFN3x3-8]
sheet 10. Mechanical parts
SCREW1  SCREW, M2, 3.5mm, PAN HEAD  [NONE]
SCREW5  SCREW, M2, 3.5mm, PAN HEAD  [NONE]
SCREW6  SCREW, M2, 3.5mm, PAN HEAD  [NONE]
SCREW7  SCREW, M2, 3.5mm, PAN HEAD  [NONE]
SP1  SPACER_SMT_2SSB-3.0  [SpacerM2H4SM]
SP2  SPACER_SMT_2SSB-3.0  [SpacerM2H4SM]
SP3  SPACER_SMT_2SSB-3.0  [SpacerM2H4SM]
SP4  SPACER_SMT_2SSB-3.0  [SpacerM2H4SM]

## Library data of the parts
C1 C25 C40 C90 C91 C132 = 100nF,_10V,_X7R,_10%,_0402: CLABCONF0: =SB-QS600
C2 C143 = 100nF,_10V,_X7R,_10%,_0402_10: CLABCONF0: =SB-QS600
C3 C22 C114 C117 C118 = 100nF,_10V,_X7R,_10%,_0402_3: CLABCONF0: =SB-QS600
C4 C27 C35 C139 = 100nF,_10V,_X7R,_10%,_0402_7: CLABCONF0: =SB-QS600
C5 C19 C57 C116 C158 = 100nF,_10V,_X7R,_10%,_0402_1: CLABCONF0: =SB-QS600
C6 C28 C41 C153 = 100nF,_10V,_X7R,_10%,_0402_8: CLABCONF0: =SB-QS600
C7 C32 C146 = 100nF,_10V,_X7R,_10%,_0402_6: CLABCONF0: =SB-QS600
C8 C112 = 100nF,_10V,_X7R,_10%,_0402_12: CLABCONF0: =SB-QS600
C9 C20 C33 C55 C133 C151 = 100nF,_10V,_X7R,_10%,_0402_2: CLABCONF0: =SB-QS600
C10 C157 = 100nF,_10V,_X7R,_10%,_0402_11: CLABCONF0: =SB-QS600
C11 C36 C141 = 100nF,_10V,_X7R,_10%,_0402_4: CLABCONF0: =SB-QS600
C12 C18 C34 C94 C136 = 100nF,_10V,_X7R,_10%,_0402_5: CLABCONF0: =SB-QS600
C21 C144 C159 = 100nF,_10V,_X7R,_10%,_0402_9: CLABCONF0: =SB-QS600
P1 = SODIMM-204_26: CLABCONF0: =SB-QS600; P/N: 190I20400S
R3 R44 R50 R71 = 10K,1%,0402,1_16W: CLABCONF0: =SB-QS600
R122 = 0R,_0402: CLABCONF0: =SB-QS600; P/N: 161F00005S
SW3 = LP_Switc_4.5x4.5mm_SMT: CLABCONF0: =SB-QS600
C13 C45 = 100nF,_10V,_X7R,_10%,_0402_4: CLABCONF0: =SB-QS600; Group: LAN2
C14 = 1nF,10%,_50V,_X7R,_0402: CLABCONF0: =SB-QS600
C15 C23 C26 C29 C37 C39 C58 C92 C160 = 1uF,X5R,6.3V,0402: CLABCONF0: =SB-QS600
C16 = 100nF,_10V,_X7R,_10%,_0402_6: CLABCONF0: =SB-QS600; Group: LAN2
C17 = 470pF,_50V,_X7R,_10%,_0603_1: CLABCONF0: =SB-QS600
C24 = 470pF,_50V,_X7R,_10%,_0603: CLABCONF0: =SB-QS600
C106 = 100pF,_50V,_NPO,_5%,_0402_3: CLABCONF0: =DNP
C107 = 100pF,_50V,_NPO,_5%,_0402_1: CLABCONF0: =DNP
C108 = 100pF,_50V,_NPO,_5%,_0402: CLABCONF0: =SB-QS600
C109 = 100pF,_50V,_NPO,_5%,_0402_2: CLABCONF0: =SB-QS600
D1 = BAT54A: CLABCONF0: =SB-QS600; P/N: 130E05403S
L26 = Ferrit_330R@100Mhz,0.2A: CLABCONF0: =DNP; P/N: 147D33100S
L27 = Ferrit_330R@100Mhz,0.2A_2: CLABCONF0: =DNP; P/N: 147D33100S
L28 = Ferrit_330R@100Mhz,0.2A_1: CLABCONF0: =SB-QS600; P/N: 147D33100S
L29 = Ferrit_330R@100Mhz,0.2A_3: CLABCONF0: =SB-QS600; P/N: 147D33100S
P2 = mini_PCIe: CLABCONF0: =SB-QS600; P/N: 182K05201S
P3 = Con.,1GBit_RJ45,_short: CLABCONF0: =SB-QS600
P4 P6 = Audio_JACK,_STEREO+AUX+SW_3.5mm: CLABCONF0: =SB-QS600
P5 = microSD_push-pull_1: CLABCONF0: =SB-QS600; P/N: 182K00803S
R1 R64 = 348R,1%,0402,1_16W_1: CLABCONF0: =SB-QS600
R2 R62 = 348R,1%,0402,1_16W: CLABCONF0: =SB-QS600
R6 = 0R,_0402_1: CLABCONF0: =SB-QS600
R5 R7 R111 = 0R,_0402: CLABCONF0: =SB-QS600
R60 R61 = 2.37K_1%,_0402: CLABCONF0: =SB-QS600
RN1 = RN,,10P8R@1206: CLABCONF0: =SB-QS600; P/N: 163I08104S
U1 U2 U9 = IP4220CZ6_0: CLABCONF0: =DNP
C30 C134 C135 C137 = Cap_1uF,X5R,6.3V,0402: CLABCONF0: =SB-QS600
C31 = 100nF,_10V,_X7R,_10%,_0402: CLABCONF0: =SB-QS600; Group: LAN2
F8-F13 = Fuse,_0.75A_Ih,_1.5A_It: CLABCONF0: =SB-QS600; P/N: 175P22200S
FB1 FB2 = Ferrite_bead_,_120_Ohm@3A: CLABCONF0: =DNP
J1 = HDMI_Connector: CLABCONF0: =SB-QS600
L1 L3-L5 = ESD_CHOKE_DIFFx2_10: CLABCONF0: =DNP; P/N: 142D11801S
Q1 Q3-Q5 Q8-Q13 = N-MOSFET,NDS335N,100mOhm@2.5V: CLABCONF0: =SB-QS600
R14 R43 R46 = 10K,1%,0402,1_16W_1: CLABCONF0: =SB-QS600
R51 = 10K,1%,0402,1_16W_2: CLABCONF0: =SB-QS600
RN2 RN3 RN6 RN7 RN10 = RN,4.7K,8P4R@0805: CLABCONF0: =SB-QS600
RN4 RN5 = RN,10K,8P4R@0805: CLABCONF0: =SB-QS600
S5 = MISC_SHORT_NL: CLABCONF0: =SB-QS600
SW1 = LP_Switc_4.5x4.5mm_SMT: CLABCONF0: =DNP
U3 U17 = IP4220CZ6_0: CLABCONF0: =SB-QS600
U24 = 7SZ07D,_buffer: CLABCONF0: =SB-QS600; P/N: 106D20070S
C38 = 1uF,X5R,6.3V,0402: CLABCONF0: =EVK
C119 = 100nF,_10V,_X7R,_10%,_0402_1: CLABCONF0: =PCIe
C120 = 100nF,_10V,_X7R,_10%,_0402_3: CLABCONF0: =PCIe
D3-D6 D12 D13 = BAT54WS: CLABCONF0: =SB-QS600
P8 = FPC_24_05mm_smt: CLABCONF0: =EVK
P9 = HDR_2x7_100MIL_RA_TH_SHRD_0: CLABCONF0: =EVK; P/N: 190C00801S
P11 = uSIM_SOCKET_0: CLABCONF0: =NOT EVK
P12 = mini_PCIe: CLABCONF0: =SB-QS600; P/N: 182K05202S
R13 R16 = 10K,1%,0402,1_16W_3: CLABCONF0: =SB-QS600
R15 R104 = 10K,1%,0402,1_16W: CLABCONF0: =DNP
R76 R97 R103 = 10K,1%,0402,1_16W_2: CLABCONF0: =DNP
R98 = 100K,_0402: CLABCONF0: =EVK; P/N: 161C10031S
R91 R109 = 0R,_0402_1: CLABCONF0: =EVK
R86 R110 = 0R,_0402_4: CLABCONF0: =DNP
R114 = 0R,_0402_6: CLABCONF0: =PCIe
R53 R115 = 0R,_0402: CLABCONF0: =DNP
R108 R118 R120 R130 R131 = 0R,_0402_2: CLABCONF0: =DNP
R132 = 0R,_0402_3: CLABCONF0: =NOT VI
R133 = 0R,_0402_5: CLABCONF0: =NOT VI
RN11 = RN,4.7K,8P4R@0805: CLABCONF0: =DNP
TP5-TP8 = TESTPOINT_0: CLABCONF0: =SB-QS600
C42 = 10pF,50V,NPO,_5%,_0402: CLABCONF0: =DNP
C43 = 10pF,50V,NPO,_5%,_0402_1: CLABCONF0: =DNP
C93 C113 = 10uF,6.3V,0603,X5R_2: CLABCONF0: =SB-QS600
C115 C125 = 10uF,6.3V,0603,X5R: CLABCONF0: =SB-QS600
C129 = 10uF,6.3V,0603,X5R_1: CLABCONF0: =SB-QS600
E1 = HDR_1x2_100MIL_TH_JUMPER: CLABCONF0: =NOT EVK
L2 L6-L9 = ESD_CHOKE_DIFFx2_10: CLABCONF0: =SB-QS600; P/N: 142D11801S
P7 = Conn.,_Micro-USB,_B-Type: CLABCONF0: =SB-QS600; P/N: 180K00502S
P13 P14 = USB_A-TYPE_DOUBLE_TH: CLABCONF0: =SB-QS600; Group: Front Panel
R89 = 10K,1%,0402,1_16W_1: CLABCONF0: =NOT EVK
R93 R119 = 0R,_0402_3: CLABCONF0: =DNP
R96 = 0R,_0402_1: CLABCONF0: =NOT EVK
R22 R41 R99 = 100K,_0402: CLABCONF0: =DNP; P/N: 161C10031S
R55 R100 = 100K,_0402_1: CLABCONF0: =SB-QS600; P/N: 161C10031S
R101 = 100K,_0402_2: CLABCONF0: =SB-QS600
R102 = 10K,1%,0402,1_16W_4: CLABCONF0: =SB-QS600
R105 = 1K,1%,0402,1_16W: CLABCONF0: =SB-QS600
R106 = 649R,1%,0402,1_16W: CLABCONF0: =SB-QS600
R134 = 0R,_0402: CLABCONF0: =NOT EVK
RN9 = RN,0R,8P4R@0805: CLABCONF0: =EVK
U4 = TMP_0: CLABCONF0: =SB-QS600
U22 = USB2_0.0_mux: CLABCONF0: =NOT EVK; P/N: 116A72220S
X1 = TMP_1: CLABCONF0: =SB-QS600
C44 = 100nF,_10V,_X7R,_10%,_0402_4: CLABCONF0: =EVK; Group: LAN2
C99 = Cap.,_47uF,_16V,_X5R: CLABCONF0: =SB-QS600; P/N: 151C10680S
L24 = ESD_CHOKE_DIFFx2_10: CLABCONF0: =EVK; P/N: 142D11801S
P16 = MINI-USB,_AB,_SMT: CLABCONF0: =EVK
R40 = 100K,_0402_1: CLABCONF0: =SB-QS600; P/N: 161C47035S
R66 = 4.99K,1%,0402,1_16W: CLABCONF0: =DNP; P/N: 161C53621S
R69 = 47K,_0402: CLABCONF0: =DNP
R87 = 0R,_0402_7: CLABCONF0: =NOT EVK
R88 = 0R,_0402_6: CLABCONF0: =NOT EVK
R90 = 0R,_0402_4: CLABCONF0: =NOT EVK
R95 = 0R,_0402_5: CLABCONF0: =NOT EVK
U5 = CP2104_0: CLABCONF0: =SB-QS600; P/N: 116A00140S
U13 = IP4220CZ6_0: CLABCONF0: =EVK
U15 = 24C02,_serial_EE,_2KB,_I2C: CLABCONF0: =SB-QS600
C59 = 100nF,_10V,_X7R,_10%,_0402_17: CLABCONF0: =VI
C60 C61 = 1uF,X5R,6.3V,0402: CLABCONF0: =VI
C62 = 10uF,6.3V,0603,X5R_1: CLABCONF0: =VI
C63 = 10uF,6.3V,0603,X5R: CLABCONF0: =VI
C64 = Cap_1uF,X5R,6.3V,0402: CLABCONF0: =VI
C65 = 100nF,_10V,_X7R,_10%,_0402_14: CLABCONF0: =VI; Group: LAN2
C66 = 100nF,_10V,_X7R,_10%,_0402_3: CLABCONF0: =VI
C67 = 100nF,_10V,_X7R,_10%,_0402_21: CLABCONF0: =VI
C68 = 100nF,_10V,_X7R,_10%,_0402_19: CLABCONF0: =VI
C69 = 100nF,_10V,_X7R,_10%,_0402_6: CLABCONF0: =VI
C70 = 100nF,_10V,_X7R,_10%,_0402_1: CLABCONF0: =VI
C71 = 100nF,_10V,_X7R,_10%,_0402_13: CLABCONF0: =VI
C72 = 100nF,_10V,_X7R,_10%,_0402_10: CLABCONF0: =VI
C73 = 100nF,_10V,_X7R,_10%,_0402: CLABCONF0: =VI
C74 = 100nF,_10V,_X7R,_10%,_0402_5: CLABCONF0: =VI
C75 = 100nF,_10V,_X7R,_10%,_0402_20: CLABCONF0: =VI
C76 = 100nF,_10V,_X7R,_10%,_0402_11: CLABCONF0: =VI
C77 = 100nF,_10V,_X7R,_10%,_0402_9: CLABCONF0: =VI
C78 = 100nF,_10V,_X7R,_10%,_0402_2: CLABCONF0: =VI
C79 = 100nF,_10V,_X7R,_10%,_0402_15: CLABCONF0: =VI
C80 = 100nF,_10V,_X7R,_10%,_0402_12: CLABCONF0: =VI
C81 = 100nF,_10V,_X7R,_10%,_0402_7: CLABCONF0: =VI
C82 C142 = 100nF,_10V,_X7R,_10%,_0402_18: CLABCONF0: =SB-QS600
C83 = 100nF,_10V,_X7R,_10%,_0402_4: CLABCONF0: =VI
C84 = 100nF,_10V,_X7R,_10%,_0402_8: CLABCONF0: =VI
C85 = Cap.,RF,5.6pF,RC0402: CLABCONF0: =VI
C86 = 15pF,_50V,_NPO,_5%,_0402: CLABCONF0: =VI
C87 = 1nF,10%,_50V,_X7R,_0402: CLABCONF0: =VI
C88 = 100nF,_10V,_X7R,_10%,_0402_16: CLABCONF0: =VI
F6 = Fuse,_0.75A_Ih,_1.5A_It: CLABCONF0: =VI; P/N: 175P22200S
J4 = MicroHDMI-D_1: CLABCONF0: =VI; P/N: 180K01902S
L10-L13 = ESD_CHOKE_DIFFx2_10: CLABCONF0: =VI; P/N: 142D11801S
L14 = Ferrit_60R@100Mhz_0.4A_0.3R_DCR_1: CLABCONF0: =VI
L15 = Ferrit_60R@100Mhz_0.4A_0.3R_DCR_7: CLABCONF0: =VI
L16 = Ferrit_60R@100Mhz_0.4A_0.3R_DCR_3: CLABCONF0: =VI
L17 = Ferrit_60R@100Mhz_0.4A_0.3R_DCR: CLABCONF0: =VI
L18 = Ferrit_60R@100Mhz_0.4A_0.3R_DCR_6: CLABCONF0: =VI
L19 = Ferrit_60R@100Mhz_0.4A_0.3R_DCR_5: CLABCONF0: =VI
L20 = Ferrit_60R@100Mhz_0.4A_0.3R_DCR_4: CLABCONF0: =VI
L21 = Ferrit_60R@100Mhz_0.4A_0.3R_DCR_2: CLABCONF0: =VI
OSC1 = Osc.,_50Mhz,50PPM,_3.3V: CLABCONF0: =VI; P/N: 141C27600S
Q6 = TRAN_2N3904_NPN_HF_SOT-23: CLABCONF0: =VI
R19 = 10K,1%,0402,1_16W_1: CLABCONF0: =VI
R20 = 22.1K_1%,_0402: CLABCONF0: =VI
R21 = 4.75K,1%,0402,1_16W: CLABCONF0: =VI
R23 = 10K,1%,0402,1_16W: CLABCONF0: =VI
R24 = 100K,_0402_1: CLABCONF0: =DNP; P/N: 161C10031S
R25 = 10K,1%,0402,1_16W_4: CLABCONF0: =VI
R26 = 1K,1%,0402,1_16W: CLABCONF0: =DNP
R27 = 1K,1%,0402,1_16W_1: CLABCONF0: =VI
R28 = 2.21k_1%_0402: CLABCONF0: =VI; P/N: 161C20011S
R29 = 33R,5%,0402,1_16W_5: CLABCONF0: =VI
R30 = 33R,5%,0402,1_16W_3: CLABCONF0: =VI
R31 = 33R,5%,0402,1_16W_1: CLABCONF0: =VI
R32 = 33R,5%,0402,1_16W_2: CLABCONF0: =VI
R33 = 33R,5%,0402,1_16W_6: CLABCONF0: =VI
R34 = 1.5K_1%,_0402: CLABCONF0: =VI
R35 = 33R,5%,0402,1_16W: CLABCONF0: =VI
R36 = 33R,5%,0402,1_16W_4: CLABCONF0: =VI
R37 = 6.81K,1%,0402,1_16W: CLABCONF0: =VI
R38 = 2K,1%,0402,1_16W: CLABCONF0: =VI; P/N: 161C12711S
R39 = 10K,1%,0402,1_16W_5: CLABCONF0: =VI
R57 = 10K,1%,0402,1_16W_3: CLABCONF0: =VI
R72 = 10K,1%,0402,1_16W_2: CLABCONF0: =VI
R73 = 1K,1%,0402,1_16W_3: CLABCONF0: =VI
R74 = 1K,1%,0402,1_16W_2: CLABCONF0: =VI
R83 = 0R,_0402_1: CLABCONF0: =VI
R84 = 0R,_0402: CLABCONF0: =VI
R107 = 0R,_0402_3: CLABCONF0: =VI
S14 = MISC_SHORT_NL: CLABCONF0: =VI
U6 U7 = RT9186A,LDO_,2.5-5_0.5V,500mA: CLABCONF0: =VI
U8 = 24C02,_serial_EE,_2KB,_I2C: CLABCONF0: =VI
U10 = TC358743XBG: CLABCONF0: =VI; P/N: 116A00160S
BT1 = ML1020: CLABCONF0: =SB-QS600; P/N: 507B010040M
C89 = 100nF_0603_2: CLABCONF0: =SB-QS600
C95 C105 = 100uF,_6.3V,_X5R,_20%,_1206: CLABCONF0: =SB-QS600
C96 = 10nF,_25V,_X7R,_10%,_0402: CLABCONF0: =SB-QS600; P/N: 151C12300S
C97 = 10nF,_25V,_X7R,_10%,_0402_1: CLABCONF0: =SB-QS600; P/N: 151C68200S
C98 = 100nF_0603: CLABCONF0: =SB-QS600
C100 = 10uF,6.3V,0603,X5R_1: CLABCONF0: =PCIe
C101 = 2.2nF,_50V,_X7R,_10%,_0402: CLABCONF0: =SB-QS600
C102 = 100nF_0603_1: CLABCONF0: =SB-QS600
C103 = Cap.,_47uF,_16V,_X5R_1: CLABCONF0: =SB-QS600
C104 = 100nF,_10V,_X7R,_10%,_0402_27: CLABCONF0: =SB-QS600
C110 = Cap.,_47uF,_16V,_X5R: CLABCONF0: =SB-QS600
C111 = 100nF,_10V,_X7R,_10%,_0402_19: CLABCONF0: =SB-QS600
C121 = 100nF,_10V,_X7R,_10%,_0402_29: CLABCONF0: =SB-QS600
C122 = 100nF,_10V,_X7R,_10%,_0402_22: CLABCONF0: =SB-QS600
C123 = 100nF,_10V,_X7R,_10%,_0402_13: CLABCONF0: =SB-QS600
C124 = 1uF,X5R,6.3V,0402: CLABCONF0: =PCIe
C138 = 100nF,_10V,_X7R,_10%,_0402_26: CLABCONF0: =SB-QS600
C140 = 100nF,_10V,_X7R,_10%,_0402_24: CLABCONF0: =SB-QS600
C145 = 100nF,_10V,_X7R,_10%,_0402_21: CLABCONF0: =SB-QS600
C147 = 100nF,_10V,_X7R,_10%,_0402_28: CLABCONF0: =SB-QS600
C148 = 100nF,_10V,_X7R,_10%,_0402_15: CLABCONF0: =SB-QS600
C149 = 100nF,_10V,_X7R,_10%,_0402_14: CLABCONF0: =SB-QS600
C150 = 100nF,_10V,_X7R,_10%,_0402_17: CLABCONF0: =SB-QS600
C152 = 100nF,_10V,_X7R,_10%,_0402_16: CLABCONF0: =SB-QS600
C154 = 100nF,_10V,_X7R,_10%,_0402_25: CLABCONF0: =SB-QS600
C155 = 100nF,_10V,_X7R,_10%,_0402_20: CLABCONF0: =SB-QS600
C156 = 100nF,_10V,_X7R,_10%,_0402_23: CLABCONF0: =SB-QS600
D2 = Diode_,MBRS340_,3A_0: CLABCONF0: =SB-QS600
DS1 = LED,_Dual,ip_3x1mm,_R_A,_G_Y_0: CLABCONF0: =SB-QS600
FB3 = Ferrite_bead_,_120_Ohm@3A: CLABCONF0: =SB-QS600
FB4 = Ferrite_bead_,_120_Ohm@3A_1: CLABCONF0: =SB-QS600
J3 = Conn._DC,_TH,_3A: CLABCONF0: =SB-QS600
L22 = IND_DELTA_MPL73-2R2_2.2uH_14A: CLABCONF0: =SB-QS600; Isat: 7; Linit: 3.3uH; P/N: 147A3R301S
L23 = Inductor_,4.7uH_,3.4A: CLABCONF0: =SB-QS600
P15 = Conn.,_W2B,_Header,_2x1,_1.25mm: CLABCONF0: =SB-QS600
Q7 Q16 = NDS332P: CLABCONF0: =DNP
R42 = 13.3K,_0402_tmp: CLABCONF0: =SB-QS600; P/N: 161C13321S
R45 = 100K,_0402_5: CLABCONF0: =DNP; P/N: 161C10031S
R47 = 47K,_0402_1: CLABCONF0: =SB-QS600
R48 = 4.99K,1%,0402,1_16W_1: CLABCONF0: =SB-QS600; P/N: 161C53621S
R49 = 3.32K,1%,0402,1_16W: CLABCONF0: =SB-QS600
R52 = 100K,_0402: CLABCONF0: =SB-QS600; P/N: 161C10031S
R56 = Res.,6.19k,1%: CLABCONF0: =SB-QS600
R58 = 4.99K,1%,0402,1_16W: CLABCONF0: =PCIe; P/N: 161C53621S
R59 = 40.2k_,1%: CLABCONF0: =SB-QS600
R63 = 100K,_0402_4: CLABCONF0: =DNP; P/N: 161C10031S
R65 = 47K,_0402: CLABCONF0: =PCIe
R67 = 100K,_0402_2: CLABCONF0: =DNP; P/N: 161C10031S
R68 = 100K,_0402_3: CLABCONF0: =SB-QS600; P/N: 161C10031S
R85 = 0R,_0402_5: CLABCONF0: =SB-QS600
R117 = 0R,_0402_3: CLABCONF0: =PCIe
R127 = 0R,_0402_1: CLABCONF0: =DNP
R128 = 0R,_0402_6: CLABCONF0: =DNP
SW2 = TactSW_4x6mm_RA_SMT: CLABCONF0: =SB-QS600
U11 = TPS54620_0: CLABCONF0: =SB-QS600
U12 = RT9186A,LDO_,2.5-5_0.5V,500mA: CLABCONF0: =SB-QS600
U14 = RT8272,Converter,3A,24V: CLABCONF0: =SB-QS600
U16 = RT9186A,LDO_,2.5-5_0.5V,500mA: CLABCONF0: =PCIe
SCREW1 SCREW5-SCREW7 = SCREW,_M2,_3.5mm,_PAN_HEAD: CLABCONF0: =SB-QS600
SP1-SP4 = Spacer,_Hex,_M2,_4mm_0.: CLABCONF0: =SB-QS600; P/N: 383B52520S

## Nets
1V2: C63.2 L15.2 L16.2 L19.1 L20.2 R21.1 U7.7(Vout1) U7.8(Vout2)
1V2ADJ: R21.2 R25.1 U7.6(ADJ)
1V5: C39.1 C40.2 C41.2 C100.2 P12.6(+1.5V_1) P12.28(+1.5V_2) P12.48(+1.5V_3) R65.1 U16.7(Vout1) U16.8(Vout2)
1V5_EN: R63.1 R117.1 R118.1 U16.4(EN)
1V5ADJ: R58.2 R65.2 U16.6(ADJ)
1V8: C59.2 C93.2 C118.2 L18.2 Q1.1(G) Q3.1(G) Q4.1(G) Q5.1(G) Q10.1(G) Q11.1(G) Q12.1(G) Q13.1(G) R3.1 R39.1 R42.1 R43.1 R44.1 R89.1 R90.2 R108.1 R110.2 RN2.5(RD2) RN2.6(RC2) RN2.7(RB2) RN2.8(RA2) RN7.5(RD2) RN7.6(RC2) RN7.7(RB2) RN7.8(RA2) RN10.5(RD2) RN10.6(RC2) RN11.5(RD2) RN11.6(RC2) RN11.7(RB2) RN11.8(RA2) U8.8(VCC) U12.7(Vout1) U12.8(Vout2) U15.8(VCC)
1V8_EN: R45.1 R85.1 R86.1 U12.4(EN)
1V8ADJ: R42.2 R46.1 U12.6(ADJ)
2V5: C62.2 C84.1 L17.1 Q6.3(COLLECTOR) R20.1 U6.7(Vout1) U6.8(Vout2)
2V5ADJ: R20.2 R23.1 U6.6(ADJ)
3V3: C18.2 C19.2 C20.2 C21.2 C22.2 C23.1 C25.1 C26.1 C27.1 C28.1 C29.1 C32.2 C33.2 C34.2 C35.2 C36.2 C37.1 C60.1 C61.1 C105.2 C111.2 C112.2 C117.2 C121.2 C122.2 C123.2 C129.2 C132.2 C133.2 C134.2 C135.2 C136.2 C138.2 C139.2 C140.2 C141.2 C142.2 C143.2 C144.2 C145.2 C146.2 C147.2 C148.2 C149.2 C150.2 C151.2 C152.2 C153.2 C154.2 C155.2 C156.2 C157.2 C158.2 D4.2(ANODE) L14.1 L21.1 L23.2 P2.2(+3.3V_1) P2.24(+3.3V_AUX) P2.39(RSVD6) P2.41(RSVD7) P2.52(+3.3V_2) P5.4(VDD) P12.2(+3.3V_1) P12.24(+3.3V_AUX) P12.39(RSVD6) P12.41(RSVD7) P12.52(+3.3V_2) R1.2 R2.2 R13.1 R14.1 R15.1 R16.1 R22.1 R24.1 R26.1 R56.1 R76.1 R99.1 R101.1 R102.1 R104.1 R107.1 R109.2 RN1.5(COM1) RN1.10(COM2) RN4.1(RA1) RN4.2(RB1) RN4.3(RC1) RN4.4(RD1) U4.5(VCCA) U4.9(VCCA) U4.14(VCCA) U4.21(VCC_D) U4.28(VREG) U6.1(Vin1) U6.2(Vin2) U6.4(EN) U7.1(Vin1) U7.2(Vin2) U7.4(EN)
3V3_CMP: C101.1 U14.6(COMP)
3V3_EN: R52.2 R55.1 U14.7(EN)
3V3_I2C: D4.1(CATHODE) RN6.5(RD2) RN6.6(RC2) RN6.7(RB2) RN6.8(RA2)
3V3_RC: C101.2 R59.1
3V3_SBT: C98.1 U14.1(BOOT)
3V3_SBYFB: R56.2 R60.1 U14.5(FB)
3V3_SS: C104.2 U14.8(SS)
3V3_SW: C98.2 D2.CATHODE L23.1 U14.3(SW)
5V: C1.1 C2.1 C3.1 C4.1 C5.1 C6.1 C7.1 C8.1 C9.1 C10.1 C11.1 C12.1 C92.1 C94.2 C95.2 C103.1 C113.2 C114.2 C115.2 C116.2 C124.1 C159.2 D3.2(ANODE) DS1.A(ANODE) F9.2 F10.2 F11.2 F12.2 L22.2 P1.10(VSYS1) P1.28(VSYS2) P1.46(VSYS3) P1.64(VSYS4) P1.78(VSYS5) P1.96(VSYS6) P1.114(VSYS7) P1.132(VSYS8) P1.150(VSYS9) P1.168(VSYS10) P1.186(VSYS11) P1.204(VSYS12) Q16.3(Drain) R48.2 R85.2 R117.2 R130.2 U12.1(Vin1) U12.2(Vin2) U14.2(Vin) U16.1(Vin1) U16.2(Vin2)
5V_BST_C: C91.2 U11.13(BOOT)
5V_CMP: R49.1 U11.8(COMP)
5V_CMP_RC: C97.1 R49.2
5V_DSP: D3.1(CATHODE) F8.2 RN3.5(RD2) RN3.6(RC2) RN3.7(RB2) RN3.8(RA2) U24.5(VCC)
5V_DSP_IN: F6.2 R27.1 R57.1 R72.1 R74.1
5V_FB: R48.1 R50.1 U11.7(VSNS)
5V_LX: C91.1 L22.1 U11.11(PH) U11.12(PH)
5V_PMOS: Q7.2(Source) Q16.2(Source)
5V_PROT1: F8.1 FB1.2 S5.1
5V_PROT_IN: F6.1 FB2.2 S14.1
5V_RT: R47.1 U11.1(RT_CLK)
5V_SB_OTG_PWR_CTRL: Q7.1(Gate) Q16.1(Gate) R67.1
5V_SS_TR: C96.2 U11.9(SS_TR)
+12V: C89.1 C102.1 C110.1 FB3.2 R67.2 R68.1 U11.4(PVIN) U11.5(PVIN) U11.6(VIN)
AVDD12: C76.2 C77.2 L19.2 U10.B2(AVDD12A) U10.D3(AVDD12B)
AVDD25: C72.2 C73.2 L17.2 U10.B5(AVDD25)
AVDD33: C80.2 C81.2 L21.2 R28.1 U10.B1(AVDD33A) U10.F3(AVDD33B)
AVDDIO1: C66.2 C67.2 L14.2 U10.F4(VDDIO1)
GND: C1.2 C2.2 C3.2 C4.2 C5.2 C6.2 C7.2 C8.2 C9.2 C10.2 C11.2 C12.2 C13.2 C14.1 C15.2 C16.2 C17.2 C18.1 C19.1 C20.1 C21.1 C22.1 C23.2 C24.2 C25.2 C26.2 C27.2 C28.2 C29.2 C30.2 C31.2 C32.1 C33.1 C34.1 C35.1 C36.1 C37.2 C38.2 C39.2 C40.1 C41.1 C42.1 C43.1 C44.2 C45.2 C55.2 C57.2 C58.1 C59.1 C60.2 C61.2 C62.1 C63.1 C64.2 C65.2 C66.1 C67.1 C68.1 C69.1 C70.1 C71.1 C72.1 C73.1 C74.1 C75.1 C76.1 C77.1 C78.1 C79.1 C80.1 C81.1 C82.2 C83.2 C84.2 C86.2 C87.1 C89.2 C90.2 C92.2 C93.1 C94.1 C95.1 C96.1 C97.2 C99.2 C100.1 C102.2 C103.2 C104.1 C105.1 C110.2 C111.1 C112.1 C113.1 C114.1 C115.1 C116.1 C117.1 C118.1 C121.1 C122.1 C123.1 C124.2 C125.1 C129.1 C132.1 C133.1 C134.1 C135.1 C136.1 C137.1 C138.1 C139.1 C140.1 C141.1 C142.1 C143.1 C144.1 C145.1 C146.1 C147.1 C148.1 C149.1 C150.1 C151.1 C152.1 C153.1 C154.1 C155.1 C156.1 C157.1 C158.1 C159.1 C160.2 D2.ANODE E1.2 FB4.2 J1.2(D2_Shield) J1.5(D1_Shield) J1.8(D0_Shield) J1.11(CK_Shield) J1.17(GND) J4.4(D2_Shield) J4.7(D1_Shield) J4.10(D0_Shield) J4.13(CK_Shield) J4.16(GND) L1.5(GND) L1.6(GND) L2.5(GND) L2.6(GND) L3.5(GND) L3.6(GND) L4.5(GND) L4.6(GND) L5.5(GND) L5.6(GND) L6.5(GND) L6.6(GND) L7.5(GND) L7.6(GND) L8.5(GND) L8.6(GND) L9.5(GND) L9.6(GND) L10.5(GND) L10.6(GND) L11.5(GND) L11.6(GND) L12.5(GND) L12.6(GND) L13.5(GND) L13.6(GND) L24.5(GND) L24.6(GND) OSC1.2(GND) P1.1(GND1) P1.19(GND2) P1.37(GND3) P1.55(GND4) P1.71(GND5) P1.87(GND6) P1.105(GND7) P1.123(GND8) P1.141(GND9) P1.159(GND10) P1.177(GND11) P1.181(RESERVED3) P2.4(GND7) P2.9(GND1) P2.15(GND2) P2.18(GND8) P2.21(GND3) P2.26(GND9) P2.27(GND4) P2.29(GND5) P2.34(GND10) P2.35(GND6) P2.37(RSVD5) P2.40(GND11) P2.50(GND12) P5.6(VSS) P5.10(M1) P5.11(M2) P5.12(M3) P5.13(M4) P7.5(GND) P8.1 P8.4 P8.7 P8.10 P8.13 P11.5(GND) P11.9(NC9) P11.10(NC10) P11.11(NC11) P11.12(NC12) P12.4(GND7) P12.9(GND1) P12.15(GND2) P12.18(GND8) P12.21(GND3) P12.26(GND9) P12.27(GND4) P12.29(GND5) P12.34(GND10) P12.35(GND6) P12.37(RSVD5) P12.40(GND11) P12.50(GND12) P13.4(GND) P13.8(GND) P14.4(GND) P14.8(GND) P15.1 P15.M1 P15.M2 P16.5(GND) Q8.2(S) Q9.2(S) R5.1 R6.1 R7.1 R19.1 R22.2 R23.2 R24.2 R25.2 R41.2 R45.2 R46.2 R47.2 R50.2 R51.2 R55.2 R58.1 R59.2 R60.2 R63.2 R66.1 R68.2 R71.1 R97.2 R98.2 R100.2 R103.2 R105.2 R106.1 R122.1 RN5.1(RA1) RN5.2(RB1) RN5.3(RC1) RN5.4(RD1) SW1.1 SW1.3 SW2.1 SW2.4 SW3.1 SW3.3 U1.2(GND) U1.5(VBUS) U2.2(GND) U2.5(VBUS) U3.2(GND) U4.29(P) U5.2(GND) U6.5(GND) U6.9(EPAD) U7.5(GND) U7.9(EPAD) U8.1(A0) U8.2(A1) U8.3(A2) U8.4(GND) U9.2(GND) U10.A2(VSSA) U10.A3(VPGM) U10.C4(VSSC) U10.C5(VSSF) U10.D4(VSSD) U10.D5(VSSG) U10.D6(VSSH) U10.E3(VSSB) U10.E4(VSSE) U10.E5(TEST) U10.E6(VSSJ) U10.H8(VSSK) U11.2(GND) U11.3(GND) U11.15(TPAD) U12.5(GND) U12.9(EPAD) U13.2(GND) U14.4(GND) U14.9(PAD) U15.1(A0) U15.2(A1) U15.3(A2) U15.4(GND) U16.5(GND) U16.9(EPAD) U17.2(GND) U22.4(GND) U22.8(\\~{O}E) U24.3(GND) X1.2(Y2) X1.4(Y4)
GND_IN: FB4.1 J3.2 J3.3
V1P7_ETH_VDDCT: C13.1 C14.2 C15.1 P1.2(3V3A_ETH_PHY) P3.P5(CT)
V3_COIN: C125.2 D12.1(CATHODE) P1.183(BACKUP_BAT) R53.1
V5_OTG: F13.1 P1.180(USBOTG_VBUS) Q7.3(Drain)
V5_OTG_CON: F13.2 P7.1(VBUS) R95.2 U17.3(IO2)
V5_UART_CON: P16.1(VBUS) R91.2 U13.3(IO2)
VBATT: D12.2(ANODE) P15.2 R53.2
VCC_USB_1: F9.1 P14.1(VBUS)
VCC_USB_2: F10.1 P14.5(VBUS)
VCC_USB_3: F11.1 P13.1(VBUS)
VCC_USB_4: F12.1 P13.5(VBUS)
VDD_MIPI: C78.2 C79.2 L20.1 U10.C6(VDD_MIPIA) U10.F6(VDD_MIPIB)
VDDC1: C70.2 C71.2 L16.1 U10.G2(VDDC1)
VDDC2: C68.2 C69.2 L15.1 U10.C3(VDDC2A) U10.F5(VDDC2B)
VDDIO2: C74.2 C75.2 L18.1 U10.H7(VDDIO2)
A_GND: C106.2 C107.2 C108.2 C109.2 P1.195(GND12) P4.1(COM) P6.1(COM) R6.2 R7.2
BIASDA: C83.1 U10.A4(BIASDA)
C1(Y): DS1.C1(Y)(CATHODE1) R62.1
C1(Y)D: Q8.3(D) R62.2
C2(G): DS1.C2(G)(CATHODE2) R64.2
C2(G)D: Q9.3(D) R64.1
C_CPU_PCIE_TX_N_C: P1.127(PCIE_TX-) P12.31(PET_N0)
C_CPU_PCIE_TX_P_C: P1.125(PCIE_TX+) P12.33(PET_P0)
CDC_HPH_LP: L27.1 P1.203(ANALOG_LOUT)
CDC_HPH_RM: L26.1 P1.201(ANALOG_ROUT)
CDC_IN2_P: P1.193(ANALOG_MICIN/MICIN-) P4.2(AUX) R61.2
CDC_IN5_P: L28.1 P1.199(ANALOG_LIN)
CDC_IN6_P: L29.1 P1.197(ANALOG_RIN)
CDC_MIC_BIAS2: P1.191(ANALOG_MICBIAS/MICIN+) R61.1
CHASSIS: J1.20(SHELL1) J1.21(SHELL2) J4.SH1 J4.SH2 J4.SH3 J4.SH4 P3.S1(SHIELD) P3.S2(SHIELD) P7.6(SHIELD1) P7.7(SHIELD2) P7.8(SHIELD3) P7.9(SHIELD4) P13.9(SHIELD) P13.10(SHIELD) P13.11(SHIELD) P13.12(SHIELD) P14.9(SHIELD) P14.10(SHIELD) P14.11(SHIELD) P14.12(SHIELD) P16.6(CHASSIS) P16.7(CHASSIS) P16.8(CHASSIS) P16.9(CHASSIS)
CLK_27MHZ: OSC1.3(OUT) R31.1
CLK_100M_EDGE_PCIE_CLK_N: P1.121(PCIE_REFCLK-) P12.11(REFCLK-)
CLK_100M_EDGE_PCIE_CLK_P: P1.119(PCIE_REFCLK+) P12.13(REFCLK+)
CLK_165M_HDMI_+: J1.10(CK+) L5.1
CLK_165M_HDMI_-: J1.12(CK-) L5.2
CLK_165M_HDMI_IN_+: J4.12(CK+) L13.1
CLK_165M_HDMI_IN_-: J4.14(CK-) L13.2
CLK_165M_HDMI_IN_N: L13.3 U10.C2(HDMICN)
CLK_165M_HDMI_IN_P: L13.4 U10.C1(HDMICP)
CLK_165M_HDMI_N: L5.3 P1.32(TMDS_CLK-)
CLK_165M_HDMI_P: L5.4 P1.30(TMDS_CLK+)
CLK_170M_0_LVDS_N: P1.35(LVDS_CLK0-) P8.12
CLK_170M_0_LVDS_P: P1.33(LVDS_CLK0+) P8.11
CLK_208M_SDC3: P1.80(SDCARD_CLK) P5.5(CLK) RN1.7(R6) U2.4(IO3)
CLK_500M_MIPI_CSI0_N: P1.109(PCAM_DAT9) U10.C7(CSICN)
CLK_500M_MIPI_CSI0_P: P1.107(PCAM_DAT8) U10.C8(CSICP)
CLKREQ#: P12.7(CLKREQ#) R115.1
CON_IN_L: C107.1 L29.2 P6.4(L)
CON_IN_R: C106.1 L28.2 P6.3(R)
CON_OUT_L: C108.1 L27.2 P4.4(L)
CON_OUT_R: C109.1 L26.2 P4.3(R)
CPU_GPIO_5: P1.130(PDISP_DAT11) RN5.5(RD2)
CPU_GPIO_22/GSBI2_3: P1.3(UART2_TX) TP5.1
CPU_GPIO_23/GSBI2_2: P1.5(UART2_RX) TP6.1
CPU_GPIO_24/GSBI2_1: P1.7(UART2_CTS) TP8.1
CPU_GPIO_25/GSBI2_0: P1.9(UART2_RTS) TP7.1
CPU_GPIO_26/SDC3_CD: P1.61(SDCARD_CD) P5.9(CD#)
CPU_GPIO_27: P1.73(PWM) R44.2 SW3.2 SW3.4
CPU_GPIO_28: P1.120(PDISP_DAT6) Q8.1(G)
CPU_GPIO_30: P1.75(RESERVED1) R83.1
CPU_GPIO_33: P1.128(PDISP_DAT10) RN5.6(RC2)
CPU_GPIO_34: P1.126(PDISP_DAT9) RN5.7(RB2)
CPU_GPIO_39: P1.124(PDISP_DAT8) RN5.8(RA2)
CPU_GPIO_51/GSBI5_3: P1.163 U10.F8(A_SD)
CPU_GPIO_52/GSBI5_2: P1.161 U10.F7(A_SCK)
CPU_GPIO_55: P1.98(PDISP_PCLK) R84.1
CPU_GPIO_86: P1.108(PDISP_DAT1) R96.1
CPU_GPIO_88: P1.138(PDISP_DAT14) Q5.2(S)
CPU_PCIE_RX_N_C: C119.2 P1.133(PCIE_RX-)
CPU_PCIE_RX_P_C: C120.2 P1.131(PCIE_RX+)
CPU_SATA_RX_N: P1.29(SATA_RX-) P2.25(PER_P0)
CPU_SATA_RX_P: P1.27(SATA_RX+) P2.23(PER_N0)
CPU_SATA_TX_N: P1.23(SATA_TX-) P2.31(PET_N0)
CPU_SATA_TX_P: P1.21(SATA_TX+) P2.33(PET_P0)
CPU_USB1_D_N: P1.178(HSUSB0_D-) RN9.4(RD1) U22.6(HSD2-)
CPU_USB1_D_P: P1.176(HSUSB0_D+) RN9.3(RC1) U22.2(HSD2+)
CPU_USB3_D_N: P1.158(HSUSB3_D-) R131.2 U4.1(UD-)
CPU_USB3_D_P: P1.160(HSUSB3_D+) R93.2 U4.2(UD+)
CPU_USB4_D_N: L9.3 P1.164(HSUSB2_D-)
CPU_USB4_D_P: L9.4 P1.166(HSUSB2_D+)
EDID_CLK: R32.1 RN10.3(RC1) U8.6(SCL)
EDID_DATA: R33.1 RN10.4(RD1) U8.5(SDA)
EEPROM_EDID_WP: R19.2 U8.7(WP)
EEPROM_WP: R71.2 U15.7(WP)
ESD_HDMI_CAP: C31.1 U3.5(VBUS)
ESD_HDMI_IN_CAP: C65.1 U9.5(VBUS)
ESD_MICRO_V: C45.1 U17.5(VBUS)
ESD_MINI_V: C44.1 U13.5(VBUS)
ETH0_CT_P6: C16.1 P3.P6(CT)
ETH0_LED0A: C24.1 P3.P14(LED2_A) R2.1
ETH0_LED1A: C17.1 P3.P12(LED1_A) R1.1
ETH0_LED1C: D1.3(CATHODE) P3.P11(LED1_C)
ETH_LED0: P1.16(ETH_LED1_SPD) P3.P13(LED2_C)
ETH_LED1: D1.1(ANODE1) P1.4(ETH_LED2_ACT) R114.2
ETH_LED2: D1.2(ANODE2) P1.22(ETH_LED3) R13.2 R115.2
ETH_TRX0_N: P1.6(MDI0-/TX-) P3.P2(MDI0-)
ETH_TRX0_P: P1.8(MDI0+/TX+) P3.P1(MDI0+)
ETH_TRX1_N: P1.12(MDI1-/RX-) P3.P4(MDI1-)
ETH_TRX1_P: P1.14(MDI1+/RX+) P3.P3(MDI1+)
ETH_TRX2_N: P1.18(MDI2-) P3.P8(MDI2-)
ETH_TRX2_P: P1.20(MDI2+) P3.P7(MDI2+)
ETH_TRX3_N: P1.24(MDI3-) P3.P10(MDI3-)
ETH_TRX3_P: P1.26(MDI3+) P3.P9(MDI3+)
H2C_BP: C85.2 Q6.1(BASE) R34.2
H2C_DAOUT: R34.1 U10.A5(DAOUT)
H2C_EP: C88.1 Q6.2(EMITTER) R38.2
H2C_INT: R84.2 U10.B3(INT)
H2C_PCKIN: C88.2 U10.B6(PCKIN)
H2C_PFIL: C86.1 R37.1 U10.A6(PFIL)
H2C_PFIL_RC: C87.2 R37.2
H2C_RC: C85.1 R38.1
H2C_REFCLK: R31.2 U10.H5(REFCLK)
H2C_RST#: R39.2 R83.2 U10.G5(RESETN)
H2CREXT: R28.2 U10.A1(REXT)
HDMI_5V: C30.1 FB1.1 J1.18(+5V) S5.2
HDMI_CEC: P1.34(HDMI_CEC) Q1.2(S) RN2.4(RD1)
HDMI_CEC_5V: J1.13(CE_Remote) Q1.3(D) RN3.1(RA1) U3.3(IO2)
HDMI_D0+: J1.7(D0+) L4.1
HDMI_D0-: J1.9(D0-) L4.2
HDMI_D1+: J1.4(D1+) L3.1
HDMI_D1-: J1.6(D1-) L3.2
HDMI_D2+: J1.1(D2+) L1.1
HDMI_D2-: J1.3(D2-) L1.2
HDMI_DDC_CLK: P1.25(TMDS_DDC_SCL) Q4.2(S) RN2.1(RA1)
HDMI_DDC_CLK_5V: J1.15(DDC_CLK) Q4.3(D) RN3.4(RD1) U3.6(IO4)
HDMI_DDC_DATA: P1.31(TMDS_DDC_SDA) Q3.2(S) RN2.2(RB1)
HDMI_DDC_DATA_5V: J1.16(DDC_DATA) Q3.3(D) RN3.3(RC1) U3.4(IO3)
HDMI_HPD: P1.40(TMDS_HPD) R43.2 U24.4(OUT)
HDMI_HPD_5V: J1.19(HP_DET) R51.1 U3.1(IO1) U24.2(IN)
HDMI_IN_5V: C64.1 FB2.1 J4.19(+5V) S14.2
HDMI_IN_CEC_5V: J4.15(CEC) U9.3(IO2) U10.G1(CEC)
HDMI_IN_D0+: J4.9(D0+) L12.1
HDMI_IN_D0-: J4.11(D0-) L12.2
HDMI_IN_D1+: J4.6(D1+) L11.1
HDMI_IN_D1-: J4.8(D1-) L11.2
HDMI_IN_D2+: J4.3(D2+) L10.1
HDMI_IN_D2-: J4.5(D2-) L10.2
HDMI_IN_DDC_CLK_5V: J4.17(DDC_CLK) R30.1 R72.2 U9.6(IO4)
HDMI_IN_DDC_DAT_5V: J4.18(DDC_DATA) R29.1 R57.2 U9.4(IO3)
HDMI_IN_HPD_5V: J4.1(HP_DET) R74.2 U9.1(IO1) U10.H1(HPDO)
HDMI_IN_TX0_N: L12.3 U10.D2(HDMID0N)
HDMI_IN_TX0_P: L12.4 U10.D1(HDMID0P)
HDMI_IN_TX1_N: L11.3 U10.E2(HDMID1N)
HDMI_IN_TX1_P: L11.4 U10.E1(HDMID1P)
HDMI_IN_TX2_N: L10.3 U10.F2(HDMID2N)
HDMI_IN_TX2_P: L10.4 U10.F1(HDMID2P)
HDMI_TX0_N: L4.3 P1.38(TMDS_DAT0-)
HDMI_TX0_P: L4.4 P1.36(TMDS_DAT0+)
HDMI_TX1_N: L3.3 P1.44(TMDS_DAT1-)
HDMI_TX1_P: L3.4 P1.42(TMDS_DAT1+)
HDMI_TX2_N: L1.3 P1.50(TMDS_DAT2-)
HDMI_TX2_P: L1.4 P1.48(TMDS_DAT2+)
HPDI: R26.2 R27.2 U10.H2(HPDI)
I2C3_SCL_3V3: P8.19 P9.6 P12.30(SMB_CLK) Q11.3(D) RN6.3(RC1)
I2C3_SDA_3V3: P8.18 P9.8 P12.32(SMB_DATA) Q10.3(D) RN6.4(RD1)
I2C5_SCL: Q13.2(S) R132.1 RN7.4(RD1)
I2C5_SCL/CPU_GPIO_54: P1.129(I2C3_SCL) R132.2 U10.G8(A_OSCK)
I2C5_SCL_3V3: P9.2 Q13.3(D) RN6.1(RA1)
I2C5_SDA: Q12.2(S) R133.1 RN7.3(RC1)
I2C5_SDA/CPU_GPIO_53: P1.135(I2C3_SDA) R133.2 U10.G7(A_WFS)
I2C5_SDA_3V3: P9.4 Q12.3(D) RN6.2(RB1)
I2C_USB_PU: R101.2 U4.26(I2C_SDA)
I2S2_MCLK/BOOT_CONFIG_1/CPU_GPIO_50: P1.185(ALT_BOOT) R3.2 R5.2 SW1.2 SW1.4
LVDS_BEN: P8.23 R98.1
LVDS_PWR: C38.1 P8.16 P8.17 P8.21 P8.22 P8.24 R109.1 R110.1 R130.1
LVDS_TX0_N: P1.41(LVDS_TX0-) P8.2
LVDS_TX0_P: P1.39(LVDS_TX0+) P8.3
LVDS_TX1_N: P1.47(LVDS_TX1-) P8.5
LVDS_TX1_P: P1.45(LVDS_TX1+) P8.6
LVDS_TX2_N: P1.53(LVDS_TX2-) P8.8
LVDS_TX2_P: P1.51(LVDS_TX2+) P8.9
LVDS_TX3_N: P1.59(LVDS_TX3-) P8.14
LVDS_TX3_P: P1.57(LVDS_TX3+) P8.15
MIPI_CSI0_LANE0_N: P1.85(PCAM_DAT7) U10.E7(CSID0N)
MIPI_CSI0_LANE0_P: P1.83(PCAM_DAT6) U10.E8(CSID0P)
MIPI_CSI0_LANE1_N: P1.91(PCAM_DAT3) U10.D7(CSID1N)
MIPI_CSI0_LANE1_P: P1.89(PCAM_DAT2) U10.D8(CSID1P)
MIPI_CSI0_LANE2_N: P1.95(PCAM_PCLK) U10.B7(CSID2N)
MIPI_CSI0_LANE2_P: P1.93(PCAM_STROBE) U10.B8(CSID2P)
MIPI_CSI0_LANE3_N: P1.115(PCAM_HSYNC) U10.A7(CSID3N)
MIPI_CSI0_LANE3_P: P1.113(PCAM_VSYNC) U10.A8(CSID3P)
mPCIE_TX_N: C119.1 P12.23(PER_N0)
mPCIE_TX_P: C120.1 P12.25(PER_P0)
MUX_OTGDN: L2.3 RN9.5(RD2) U22.5(D-)
MUX_OTGDP: L2.4 RN9.6(RC2) U22.3(D+)
MUX_VCC: R134.1 U22.9(VCC)
OC#1_PU: RN4.8(RA2) U4.25(OVR#[1])
OC#2_PU: RN4.7(RB2) U4.24(OVR#[2])
OC#3_PU: RN4.6(RC2) U4.20(OVR#[3])
OC#4_PU: RN4.5(RD2) U4.19(OVR#[4])
OSC_EN: OSC1.1(EN) R73.1
OTGDN: L2.2 P7.2(D-) U17.6(IO4)
OTGDP: L2.1 P7.3(D+) U17.4(IO3)
PCI_W_DISABLE#: P12.20(RSVD18) R76.2
PERST#: P12.22(PERST#) R15.2
PMIC_BMS_CSP: P1.179(RESERVED2) R122.2
PMIC_MPP_8821_9: P1.200(RESERVED6) P8.20
PWR_SW: D5.1(CATHODE) D6.1(CATHODE) R127.2 R128.2 SW2.2 SW2.3
PWRBTN#: D5.2(ANODE) P1.165(PWRON) R128.1
R_DDC_SCL: R30.2 U10.H3(DDC_SCL)
R_DDC_SDA: R29.2 U10.G3(DDC_SDA)
R_EDID_SCL: R32.2 U10.H6(EDID_SCL)
R_EDID_SDA: R33.2 U10.G6(EDID_SDA)
R_I2C_SCL: R35.2 U10.H4(I2C_SCL)
R_I2C_SDA: R36.2 U10.G4(I2C_SDA)
RS232_RXD: P1.117(RS232_RX) R119.1 U5.21(TXD)
RS232_TXD: P1.111(RS232_TX) R120.1 U5.20(RXD)
RSTBTN#: D6.2(ANODE) P1.171(COLD_RESET_IN) R127.1
SDC3_CMD: P1.82(SDCARD_CMD) P5.3(CMD) RN1.6(R5) U2.6(IO4)
SDC3_DATA_0: P1.84(SDCARD_DAT0) P5.7(DAT0) RN1.1(R1) U1.1(IO1)
SDC3_DATA_1: P1.86(SDCARD_DAT1) P5.8(DAT1) RN1.2(R2) U1.3(IO2)
SDC3_DATA_2: P1.88(SDCARD_DAT2) P5.1(DAT2) RN1.3(R3) U1.4(IO3)
SDC3_DATA_3: P1.90(SDCARD_DAT3) P5.2(DAT3) RN1.4(R4) U1.6(IO4)
SIM_CLK: P11.3(CLK) P12.12(RSVD15)
SIM_IO: P11.7(IO) P12.10(RSVD14)
SIM_RST: P11.2(RST) P12.14(RSVD16)
SIM_VCC: P11.1(VCC) P12.8(RSVD13)
SIM_VPP: P11.6(VPP) P12.16(RSVD17)
SPI3_CLK/CPU_GPIO_9/GSBI3_0: P1.69(SPI_CLK) Q11.2(S) R35.1 RN7.2(RB1) U15.6(SCL)
SPI3_CS_N/CPU_GPIO_8/GSBI3_1: P1.58(SPI_CS0) Q10.2(S) R36.1 RN7.1(RA1) U15.5(SDA)
SPI4_CLK/CPU_GPIO_13/GSBI4_0: P1.66(RTOUCH_X+) P9.1 RN11.1(RA1)
SPI4_CS_N/CPU_GPIO_12/GSBI4_1: P1.68(RTOUCH_X-) P9.3 RN11.2(RB1)
SPI4_MISO/CPU_GPIO_11/GSBI4_2: P1.72(RTOUCH_Y-) P9.7 RN11.4(RD1)
SPI4_MOSI/CPU_GPIO_10/GSBI4_3: P1.70(RTOUCH_Y+) P9.5 RN11.3(RC1)
TEST_USB: R104.2 R105.1 U4.18(TEST)
UART_RST: C99.1 D13.2(ANODE) R40.2 R41.1 U5.9(RST#)
UARTDN: L24.3 R87.1 U5.4(DN)
UARTDN_CON: L24.2 P16.2(D-) R119.2 U13.4(IO3)
UARTDP: L24.4 R88.1 U5.3(DP)
UARTDP_CON: L24.1 P16.3(D+) R120.2 U13.6(IO4)
UARTREGIN: C90.1 C160.1 R111.1 U5.7(REGIN)
UARTVBUS: R91.1 R95.1 R111.2 U5.8(VBUS)
UARTVDD: C57.1 C137.2 D13.1(CATHODE) R40.1 R69.1 R134.2 U5.6(VDD)
UARTVDD_VIO: C55.1 R66.2 R69.2 R90.1 U5.5(VIO)
UARTVPP: C58.2 U5.16(VPP)
USB1_ID: P1.174(USBOTG_ID) P7.4(ID)
USB1N_C: L6.2 P14.2(D-)
USB1P_C: L6.1 P14.3(D+)
USB2N_C: L7.2 P14.6(D-)
USB2P_C: L7.1 P14.7(D+)
USB3N_C: L8.4 P13.2(D-)
USB3P_C: L8.3 P13.3(D+)
USB4N_C: L9.2 P13.6(D-)
USB4P_C: L9.1 P13.7(D+)
USB_GANG_PD: R99.2 R100.1 U4.23(GANG)
USB_HUB_RESET#: Q5.3(D) R16.2 U4.17(RESET#)
USB_mPCIe_DM: P12.36(USB_D-) U4.15(DD-4)
USB_mPCIe_DP: P12.38(USB_D+) U4.16(DD+4)
USB_RREF: R106.2 U4.8(RREF)
USB_SELF_PWR: R102.2 R103.1 U4.22(SELFPWR)
USB_UART_D_N: R87.2 U22.7(HSD1-)
USB_UART_D_P: R88.2 U22.1(HSD1+)
USBDN1_DM: L6.3 U4.3(DD-1)
USBDN1_DP: L6.4 U4.4(DD+1)
USBDN2_DM: L7.3 U4.6(DD-2)
USBDN2_DP: L7.4 U4.7(DD+2)
USBDN3_DM: L8.1 R131.1 U4.12(DD-3)
USBDN3_DP: L8.2 R93.1 U4.13(DD+3)
USBMUXSEL: E1.1 R89.2 R96.2 U22.10(SEL)
V_OSC: C82.1 OSC1.4(VCC) R73.2 R107.2 R108.2
VAC_BRCK_IN: FB3.1 J3.1
VPH: P1.140(PDISP_DAT15) P1.192(RESERVED4) Q9.1(G) R52.1 R86.2 R97.1 R118.2
WAKE#: P12.1(WAKE#) R14.2 R114.1
XTAL12_IN: C42.2 U4.10(XIN) X1.3(Y3)
XTAL12_OUT: C43.2 U4.11(XOUT) X1.1(Y1)

Not connected (* = marked no-connect by the designer): BT1 1(POS)* 2(NEG)*; J1 14(NC)*; J4 2(NC/UTILITY)*; P1 11(UART1_TX)* 13(UART1_RX)* 15(UART1_CTS)* 17(UART1_RTS)* 43(I2C2_SCL)* 49(I2C2_SDA)* 52(SPI_CS1)* 54* 56* 60* 62* 63(SPI_SOMI)* 65(SPI_SIMO)* 67(SDCARD_WP)* 74(PDISP_DAT22)* 76(PDISP_DAT23)* 77(PCAM_DAT4)* 79(PCAM_DAT5)* 81(PCAM_SHUTTER)* 92(PDISP_DAT17)* 94(PDISP_DAT16)* 97(PCAM_WEN)* 99(PCAM_RESET)* 100(PDISP_HSYNC)* 101(PCAM_DAT0)* 102(PDISP_VSYNC)* 103(PCAM_DAT1)* 104(PDISP_DE)* 106(PDISP_DAT0)* 110(PDISP_DAT2)* 112(PDISP_DAT3)* 116(PDISP_DAT4)* 118(PDISP_DAT5)* 122(PDISP_DAT7)* 134(PDISP_DAT12)* 136(PDISP_DAT13)* 137(I2S1_CLKX)* 139(I2S1_DOUT)* 142(PDISP_DAT18)* 143(I2S1_DIN)* 144(PDISP_DAT19)* 145(I2S1_FSX)* 146(PDISP_DAT20)* 147(SDIO_CMD)* 148(PDISP_DAT21)* 149(SDIO_DAT3)* 151(SDIO_DAT2)* 152(GPIO1)* 153(SDIO_DAT1)* 154(GPIO2)* 155(SDIO_DAT0)* 156(USB_PWREN)* 157(SDIO_CLK)* 162(USB_nOVC)* 167* 169* 170(HSUSB1_D-)* 172(HSUSB1_D+)* 173* 175* 182(SSUSB_RX+)* 184(SSUSB_RX-)* 187(nRESET_WARM)* 188(SSUSB_TX+)* 189(EEPROM_WP)* 190(SSUSB_TX-)* 194(RESERVED5)* 196(BOOT_PWR_IN)* 198(PER_PWREN_OUT)* 202(PER_PWREN_REQ)*; P2 1(WAKE#)* 3(RSVD1)* 5(RSVD2)* 6(+1.5V_1)* 7(CLKREQ#)* 8(RSVD13)* 10(RSVD14)* 11(REFCLK-)* 12(RSVD15)* 13(REFCLK+)* 14(RSVD16)* 16(RSVD17)* 17(RSVD3)* 19(RSVD4)* 20(RSVD18)* 22(PERST#)* 28(+1.5V_2)* 30(SMB_CLK)* 32(SMB_DATA)* 36(USB_D-)* 38(USB_D+)* 42(LED_WWAN#)* 43(RSVD8)* 44(LED_WLAN#)* 45(RSVD9)* 46(LED_WPAN#)* 47(RSVD10)* 48(+1.5V_3)* 49(RSVD11)* 51(RSVD12)*; P4 CN* CO*; P6 2(AUX)* CN* CO*; P11 4(NC4)* 8(NC8)*; P12 3(RSVD1)* 5(RSVD2)* 17(RSVD3)* 19(RSVD4)* 42(LED_WWAN#)* 43(RSVD8)* 44(LED_WLAN#)* 45(RSVD9)* 46(LED_WPAN#)* 47(RSVD10)* 49(RSVD11)* 51(RSVD12)*; P16 4(ID)*; RN1 8(R7)* 9(R8)*; RN2 3(RC1)*; RN3 2(RB1)*; RN9 1(RA1)* 2(RB1)* 7(RB2)* 8(RA2)*; RN10 1(RA1)* 2(RB1)* 7(RB2)* 8(RA2)*; SP1 1*; SP2 1*; SP3 1*; SP4 1*; U2 1(IO1)* 3(IO2)*; U4 27(VCC)*; U5 1(RI)* 10(NC)* 11(GPIO3)* 12(GPIO2)* 13(GPIO1)* 14(GPIO0)* 15(SUSPEND#)* 17(SUSPEND)* 18(CTS)* 19(RTS)* 22(DSR)* 23(DTR)* 24(DCD)*; U6 3(PGOOD)*; U7 3(PGOOD)*; U10 B4(IR)* MH1* MH2* MH3* MH4* MH5* MH6*; U11 10(EN)* 14(PWRGD)*; U12 3(PGOOD)*; U13 1(IO1)*; U16 3(PGOOD)*; U17 1(IO1)*

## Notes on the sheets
sheet 1
- SB-QS600 rev 1.2
- PAGE
- FUNCTION
- 01
- INDEX
- 02
- SODIMM
- 03
- CONNECTORS 1
- 04
- CONNECTORS 2
- 05
- CONNECTORS 3
- 06
- USB_HUB
- 07
- UART2USB
- 08
- HDMI2CSI
- 09
- PWR
- 10
- Mechanical parts
- I2C addresses
- PAGE
- FUNCTION
- 50H
- EEPROM
sheet 2
- H2C_INT
- USB_MUX SEL
- STBY_LED
- BOOTSTRAP
- BOOTSTRAP
- BOOTSTRAP
- MIC_I2S_MCLK
- BOOTSTRAP
- MIC_I2S_WS
- USB_HUB_RESET#
- MIC_I2S_SCK
- MIC_I2S_DIN
- 2A
- Rsns
- 2A
- PMIC_BMS_CSN
- 20 mil trace
- LVDS_MPP
sheet 3
- mSATA
- ETHERNET CM
- AUDIO
- MMC\SD CARD (boot)
- OUT
- SDIO 3
- 20 mil trace
- Place ACAP to P4-1
- IN
- DNP
- DNP
- 20 mil trace
- Place ACAP to P6-1
sheet 4
- HDMI CM
- DNP
- HDMI LEVEL TRANS
- BOOT STRAP
- HPD
- DNP all if bootstrap fuses blown on CM-QS600
- DNP
- To disable alt boot option:
  DNP R5 res
  For ATP board only:
  Populate SW1. DNP R5
sheet 5
- LVDS
- I2C 3V3 LEVEL TRANS
- GSBI4 + I2C
- DNP
  Provision for I2C
- GSBI4 is 1.8V LVL
- EVK OPT
- DNP IF VIDEO IN ASSEMBLED
- GSBI2 is 1.8V LVL
- DNP IF VIDEO IN ASSEMBLED
- Place TP as a close group
- EVK OPT
- DNP
- DNP
- CP
- EVK OPT
- mPCIe
- uSIM
- PCIe OPT
- DNP ALWAYS
- DNP
- PCIe OPT
- PCIe OPT
- When used with CM-QS600 w/o PCIe option (default),
  only USB interface available on P12 connector.
- Populate R0 resistors on ETH_LED# signals only
  when PCIe option available on CM-QS600
  ETH_LED# signals are 3V3 tolerant
sheet 6
- USB POWER
- DNP
- CP
- CP
- DNP
- DNP
- USB CONNECTORS
- CP
- H0.8
- REAR
- DNP
- DNP
- FRONT
- Sourced from USB2UART REG
- USB OTG
- NOT EVK OPT
- USB HUB BYPASS
- NOT EVK OPT
- DNP
- DNP
- Place R0 AsCloseAsPosible to the HUB's pins 13,14
  Don't replace with RN!!!
- NOT EVK OPT
- USB OTG CONN
- USB MUX BYPASS
- NOT EVK OPT
- EVK OPT
- NOT EVK OPT
- Place RN AsCloseAsPosible to the MUX
- EVK OPT: MINI-USB CONNECTOR DEDICATED TO DEBUG INTERFACE
  NOT EVK OPT: DEBUG INTERFACE MUXED WITH OTG ON A SINGLE MICRO-USB CONNECTOR
sheet 7
- UART2USB
- DNP
- DNP
- Place ACAP
  to L24
- Place ACAP
  to L24
- EVK OPT
- EVK OPT
- EVK OPT
- H 0.8
- EVK OPT
- DNP
  Place holder
- VBUS/SELF powered system provisions
- UART2USB BYPASS
- SB EEPROM
- NOT EVK OPT
- DNP
- EVK OPT
- CP R95 and R91
- DNP
- DNP
- VBUS powered as default
  For self powered refer
  CP2104 DS p18 note 5
  DNP depends on external
   usb connector used
- PU on page 5
- PU on page 5
- EVK OPT: MINI-USB CONNECTOR DEDICATED TO DEBUG INTERFACE
  NOT EVK OPT: DEBUG INTERFACE MUXED WITH OTG ON A SINGLE MICRO-USB CONNECTOR
- I2C: 50h
sheet 8
- HDMI2CSI (HDMI IN)
- HDMI IN
- 2V5_DC 500mA
- 1V2_DC 500mA
- EDID EEPROM
- 0.8*(1+22.1/10)=2.568V
- 0.8*(1+4.75/10)=1.18V
- H 1mm
- H 1mm
- DNP
- DNP
- DNP
- DNP
- I2C: 50h
- IC HAS A DUAL 1.8V-3.3V INTERFACE
- Place REXT beneath
  balls B1 and A1
- DNP
- Intralane match 28 mil
  Interlane match 140 mil
- CP
- CP
- DNP
- Intralane match 28 mil
  Interlane match 140 mil
- Audio PLL
sheet 9
- 5V@6A
- OTG SB POWER SOURCE SELECT
- 1V8_DC 500mA
- PROVISION
- 0.8*(1+13.3/10)=1.864V
- DNP
- DNP
- 2A
- 2A
- 2A
- DNP
- CP
- 1Mhz
- DNP
- Vref=0.8V
- DNP
- POWER
  3.3V UP TO 3A
- 1V5_DC 500mA PCIe OPT
- POWER
  JACK
- 0.8*(1+47/53.6)=1.501V
- DNP
- CP
- Von > 1.4V OR NC
- Internall PU
- DNP
- RTC BACKUP
    POWER
- 5V for
  HDMI DDC
- POWER LEDS
- ON/OFF
- DNP
- DNP
- DNP
- DNP
sheet 10
- MECHANIC SPACERS
- 3.5mm SCREWS
sheet 11
- SB-QS600 rev 1.2
  Change notes
- Date
- Description
- Added OTG_VBUS supply option to USB MUX
  Dedicated HDMI_5V_IN source, added PU to DDC
  Fixed LVDS I2C net names
  PCIe I2C channel changed to I2C3
  Added R0 to MUX VCC
  Shorted R92
  Added R0 serial res to I2C5 to isolate channel in VI opt
